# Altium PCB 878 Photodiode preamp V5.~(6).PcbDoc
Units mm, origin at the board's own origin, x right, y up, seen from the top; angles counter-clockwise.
Board outline 114 x 114 mm, 6 copper layers (Top Layer, Internal Plane 1, Dummy Ground, Dummy Power, Internal Plane 2, Bottom Layer), stack 0.534 mm thick; 182 components, 82 nets, 481 pads, 78 vias.
Unrouted connection lines stored in the file: 13.
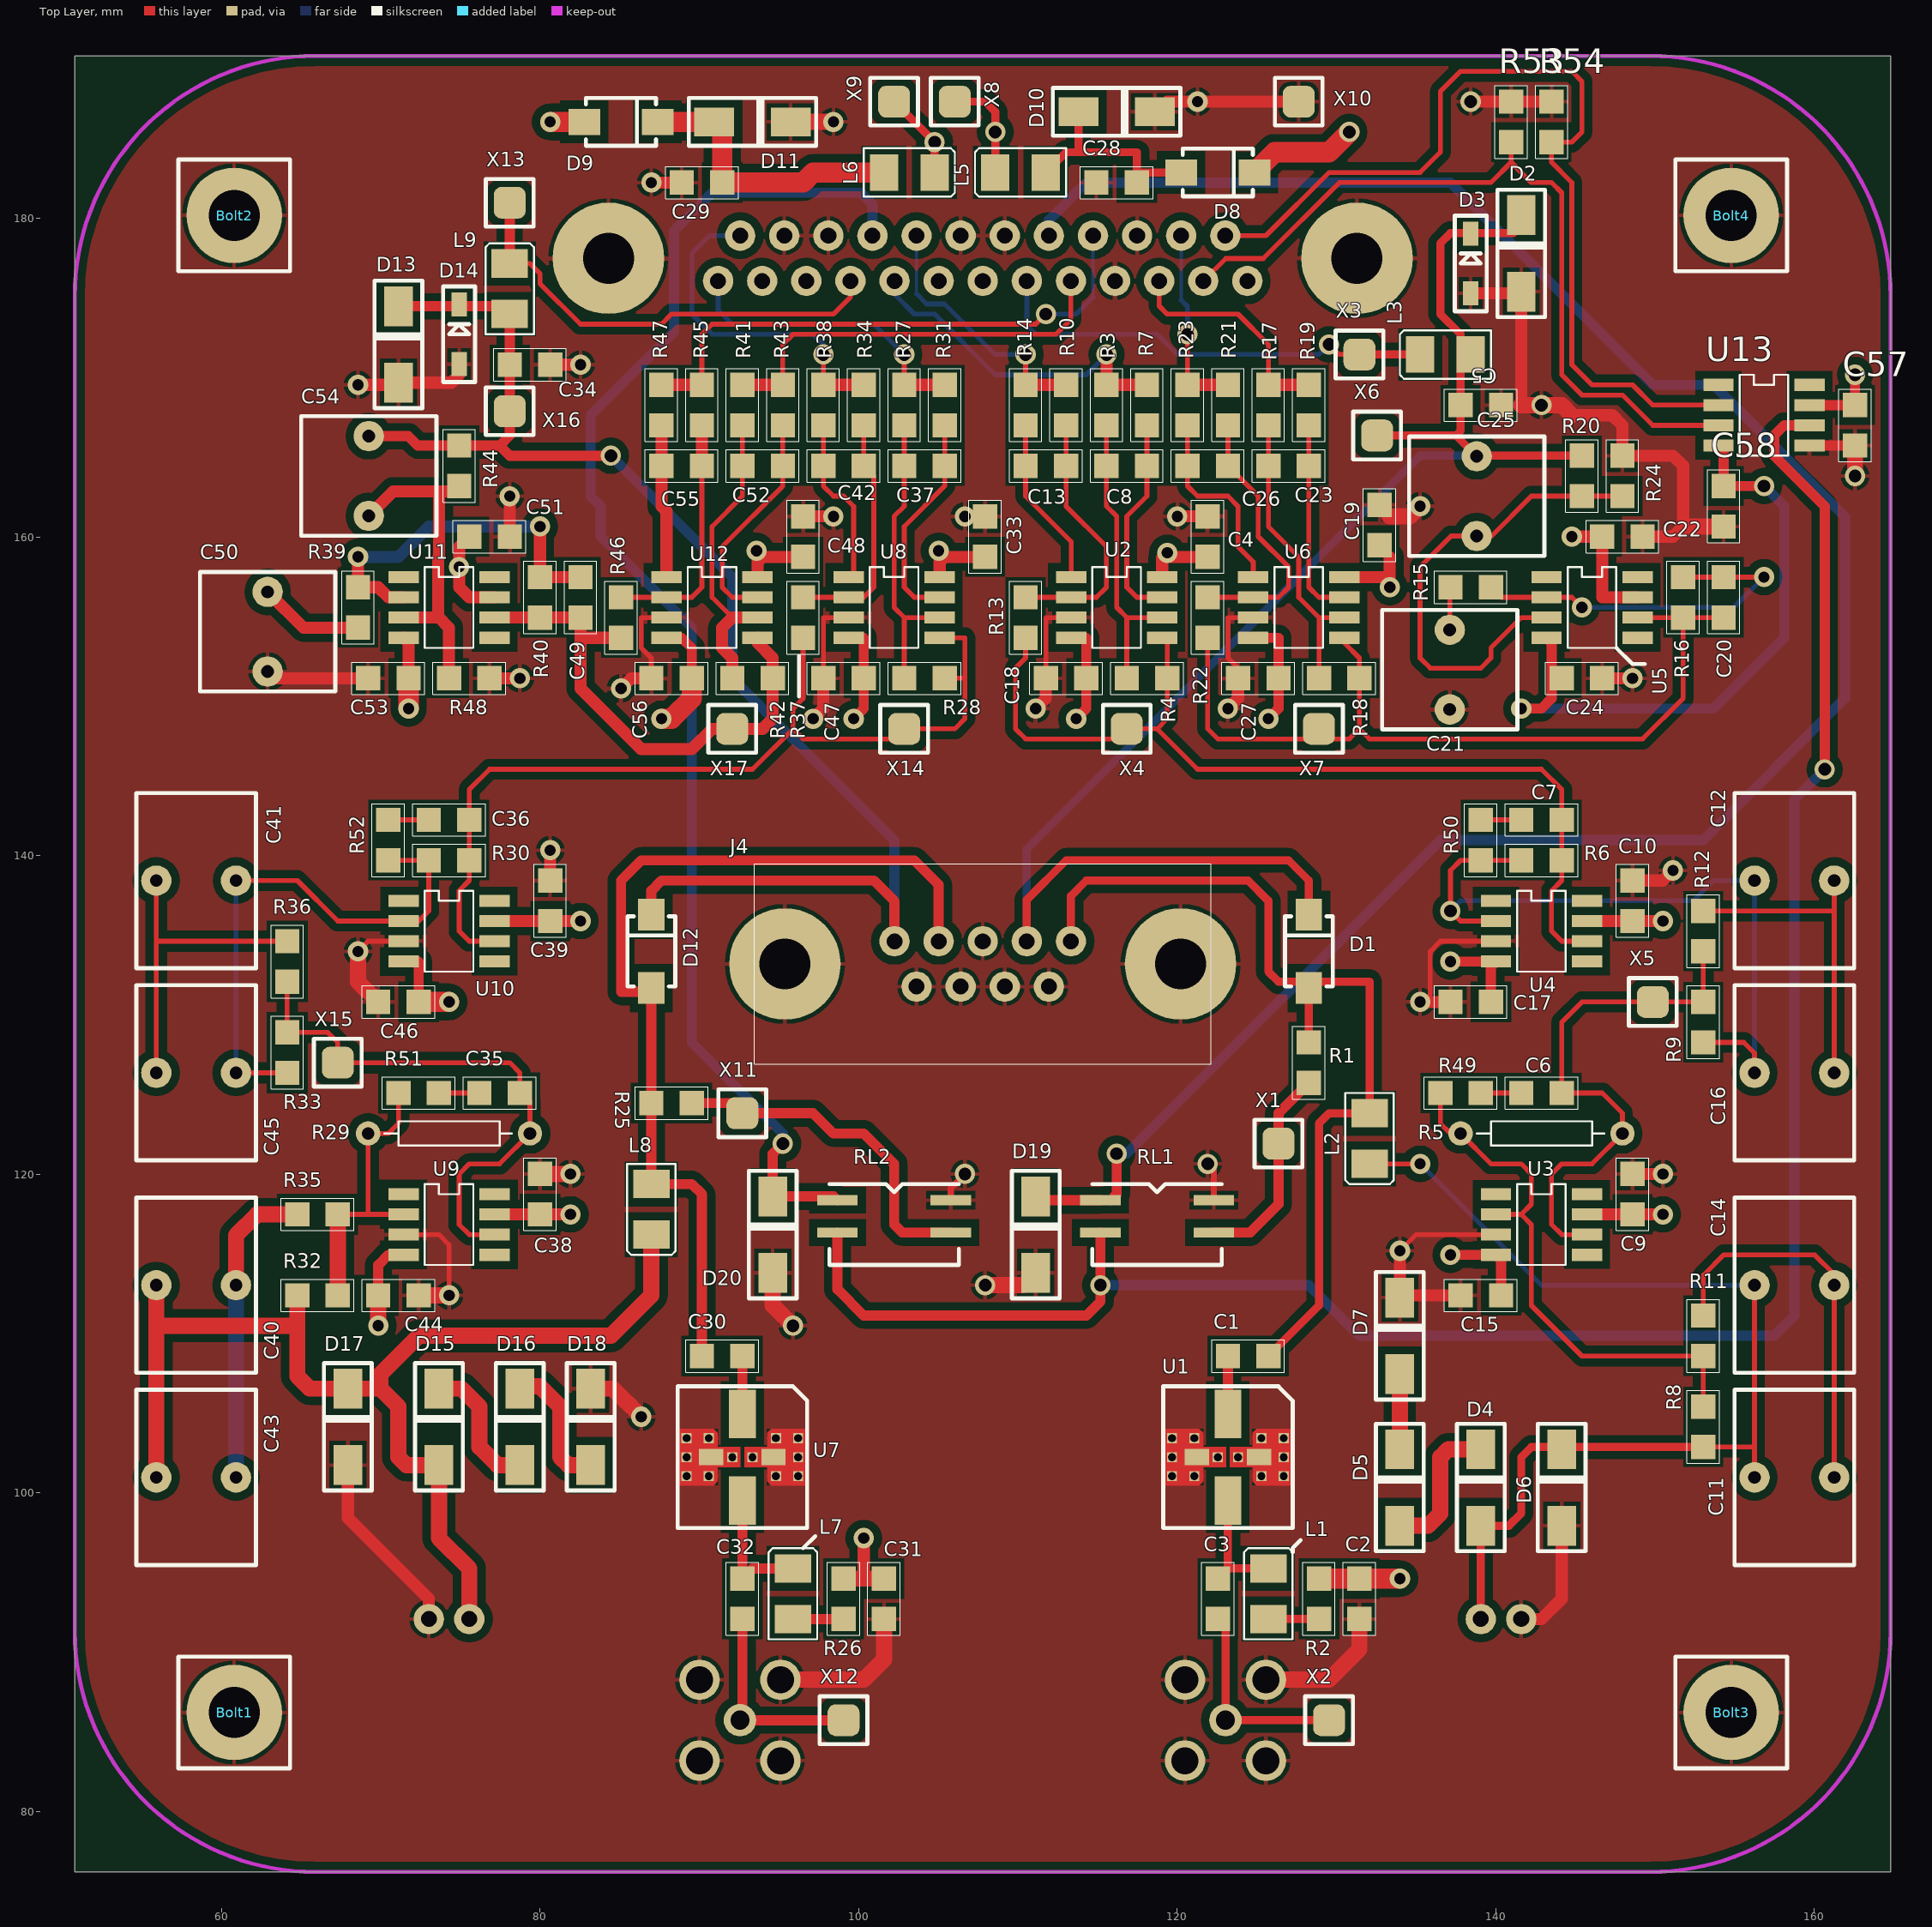
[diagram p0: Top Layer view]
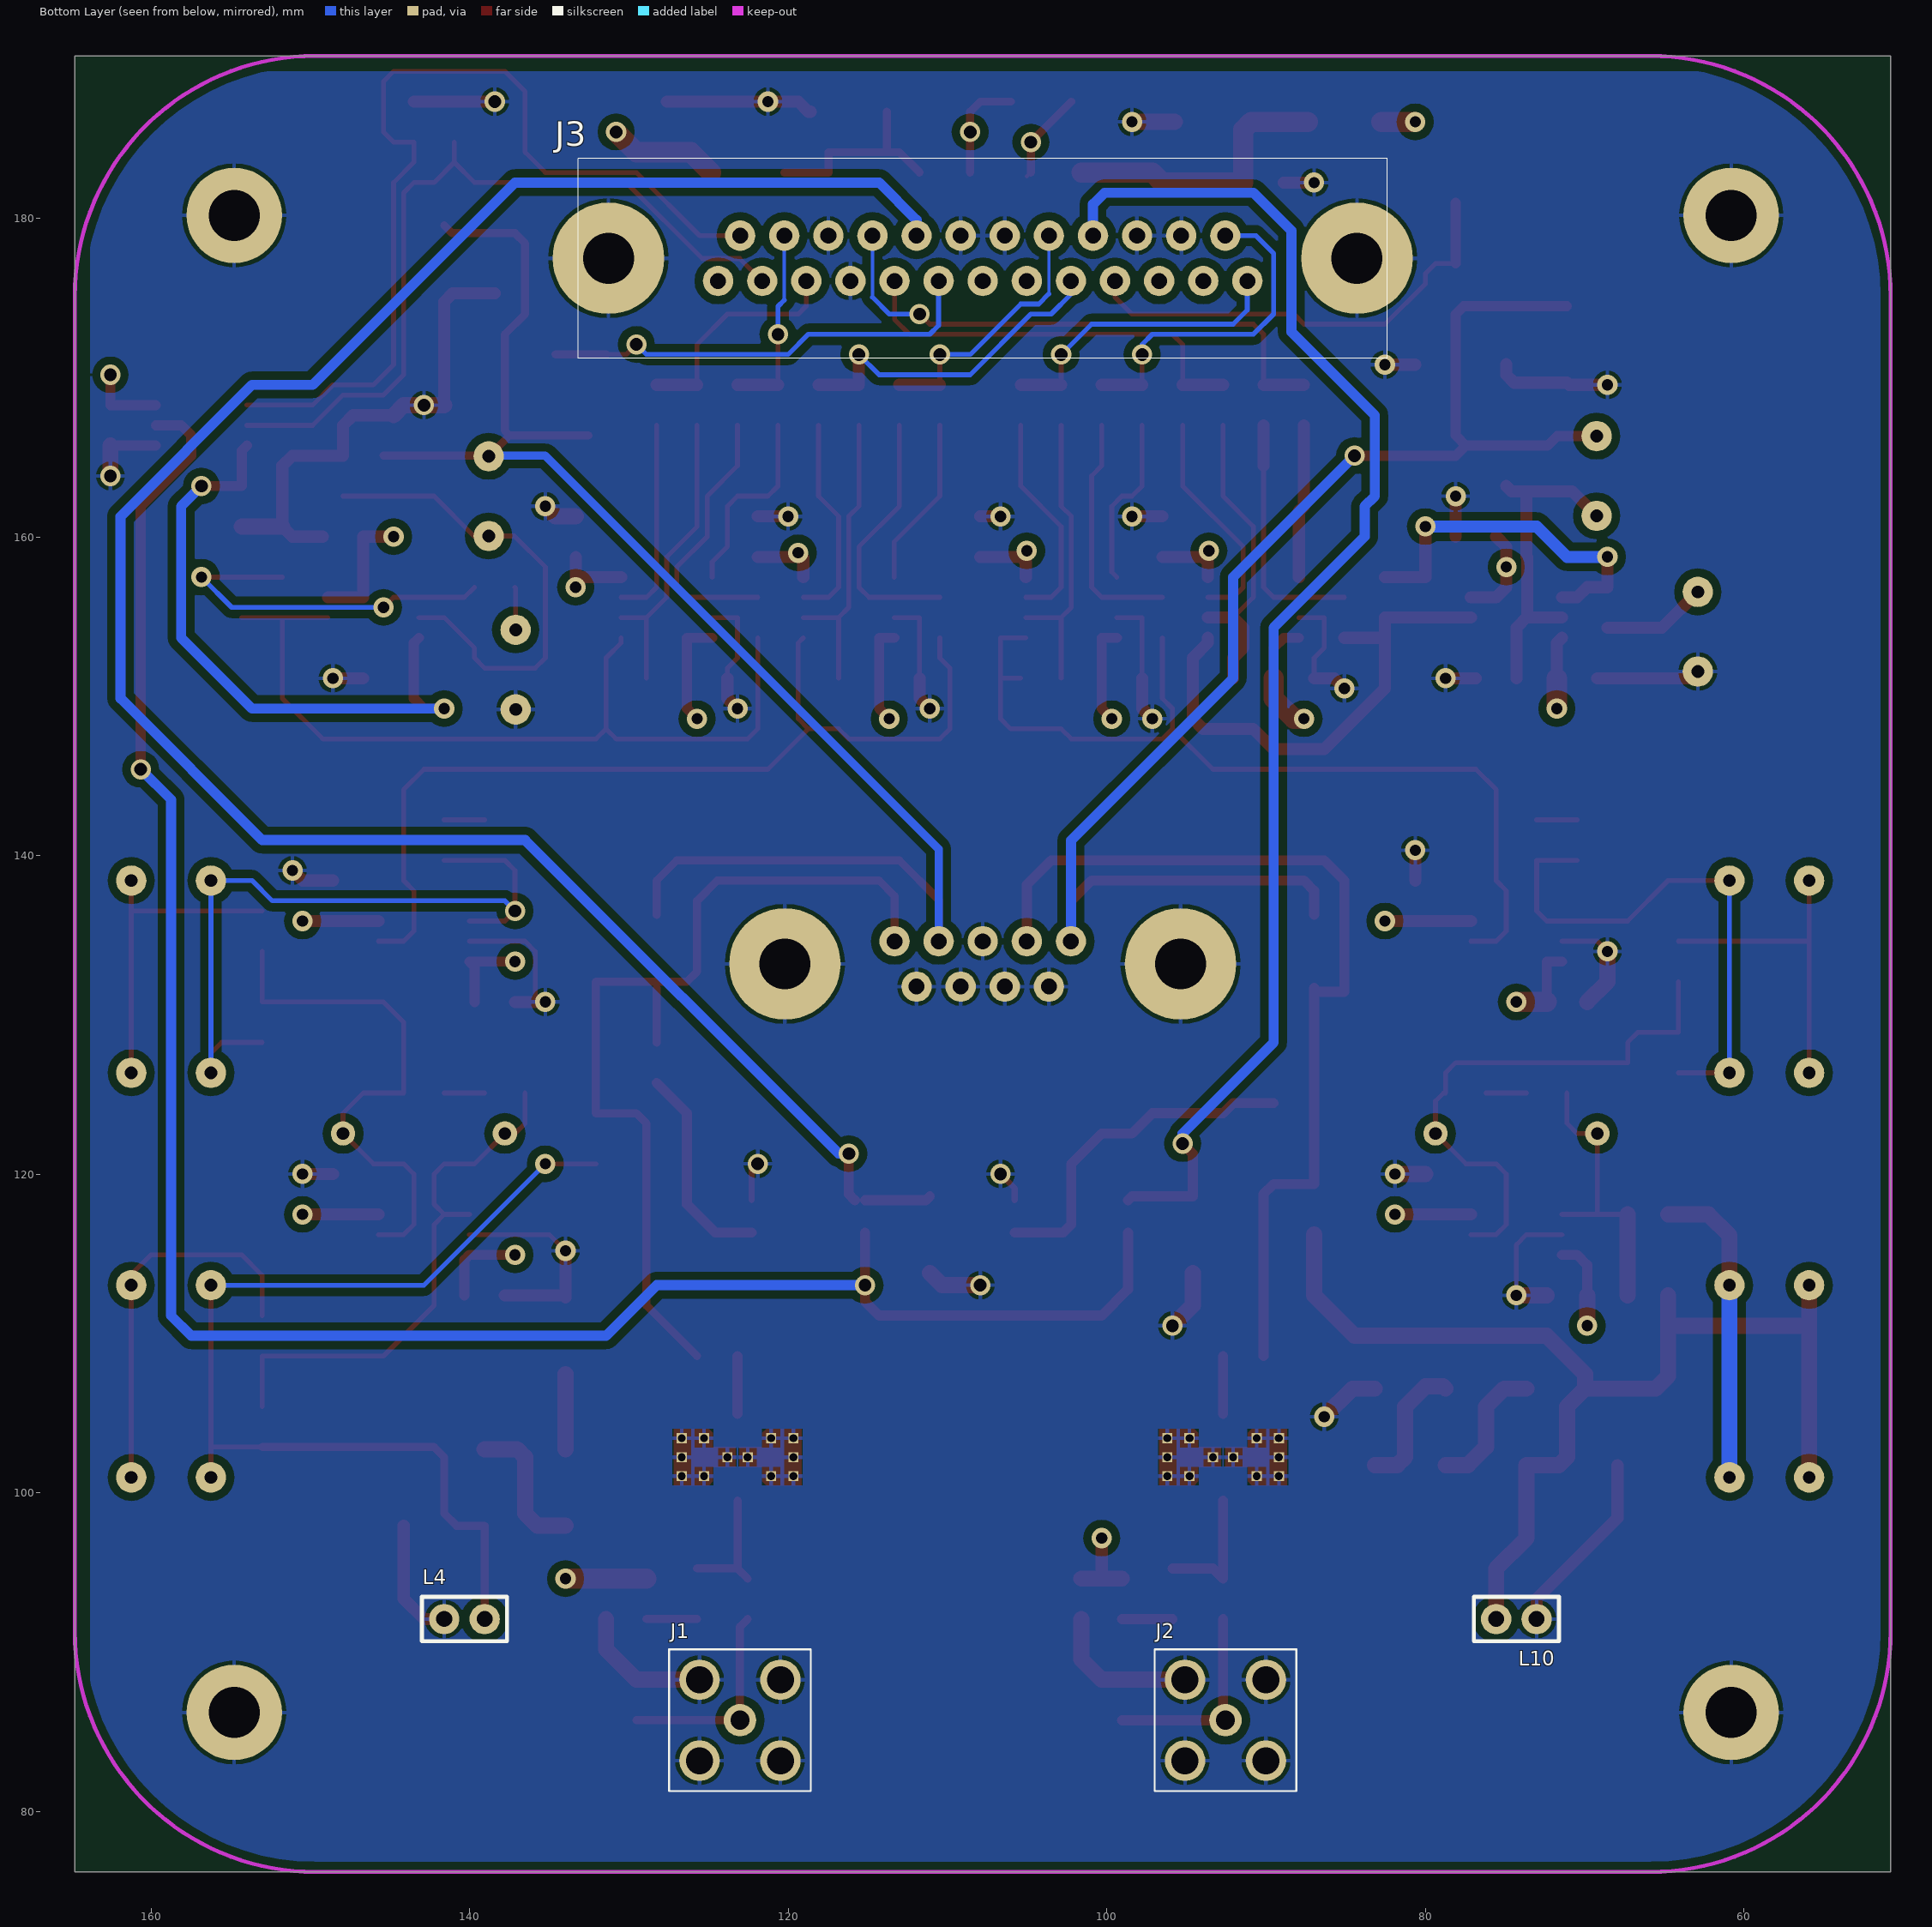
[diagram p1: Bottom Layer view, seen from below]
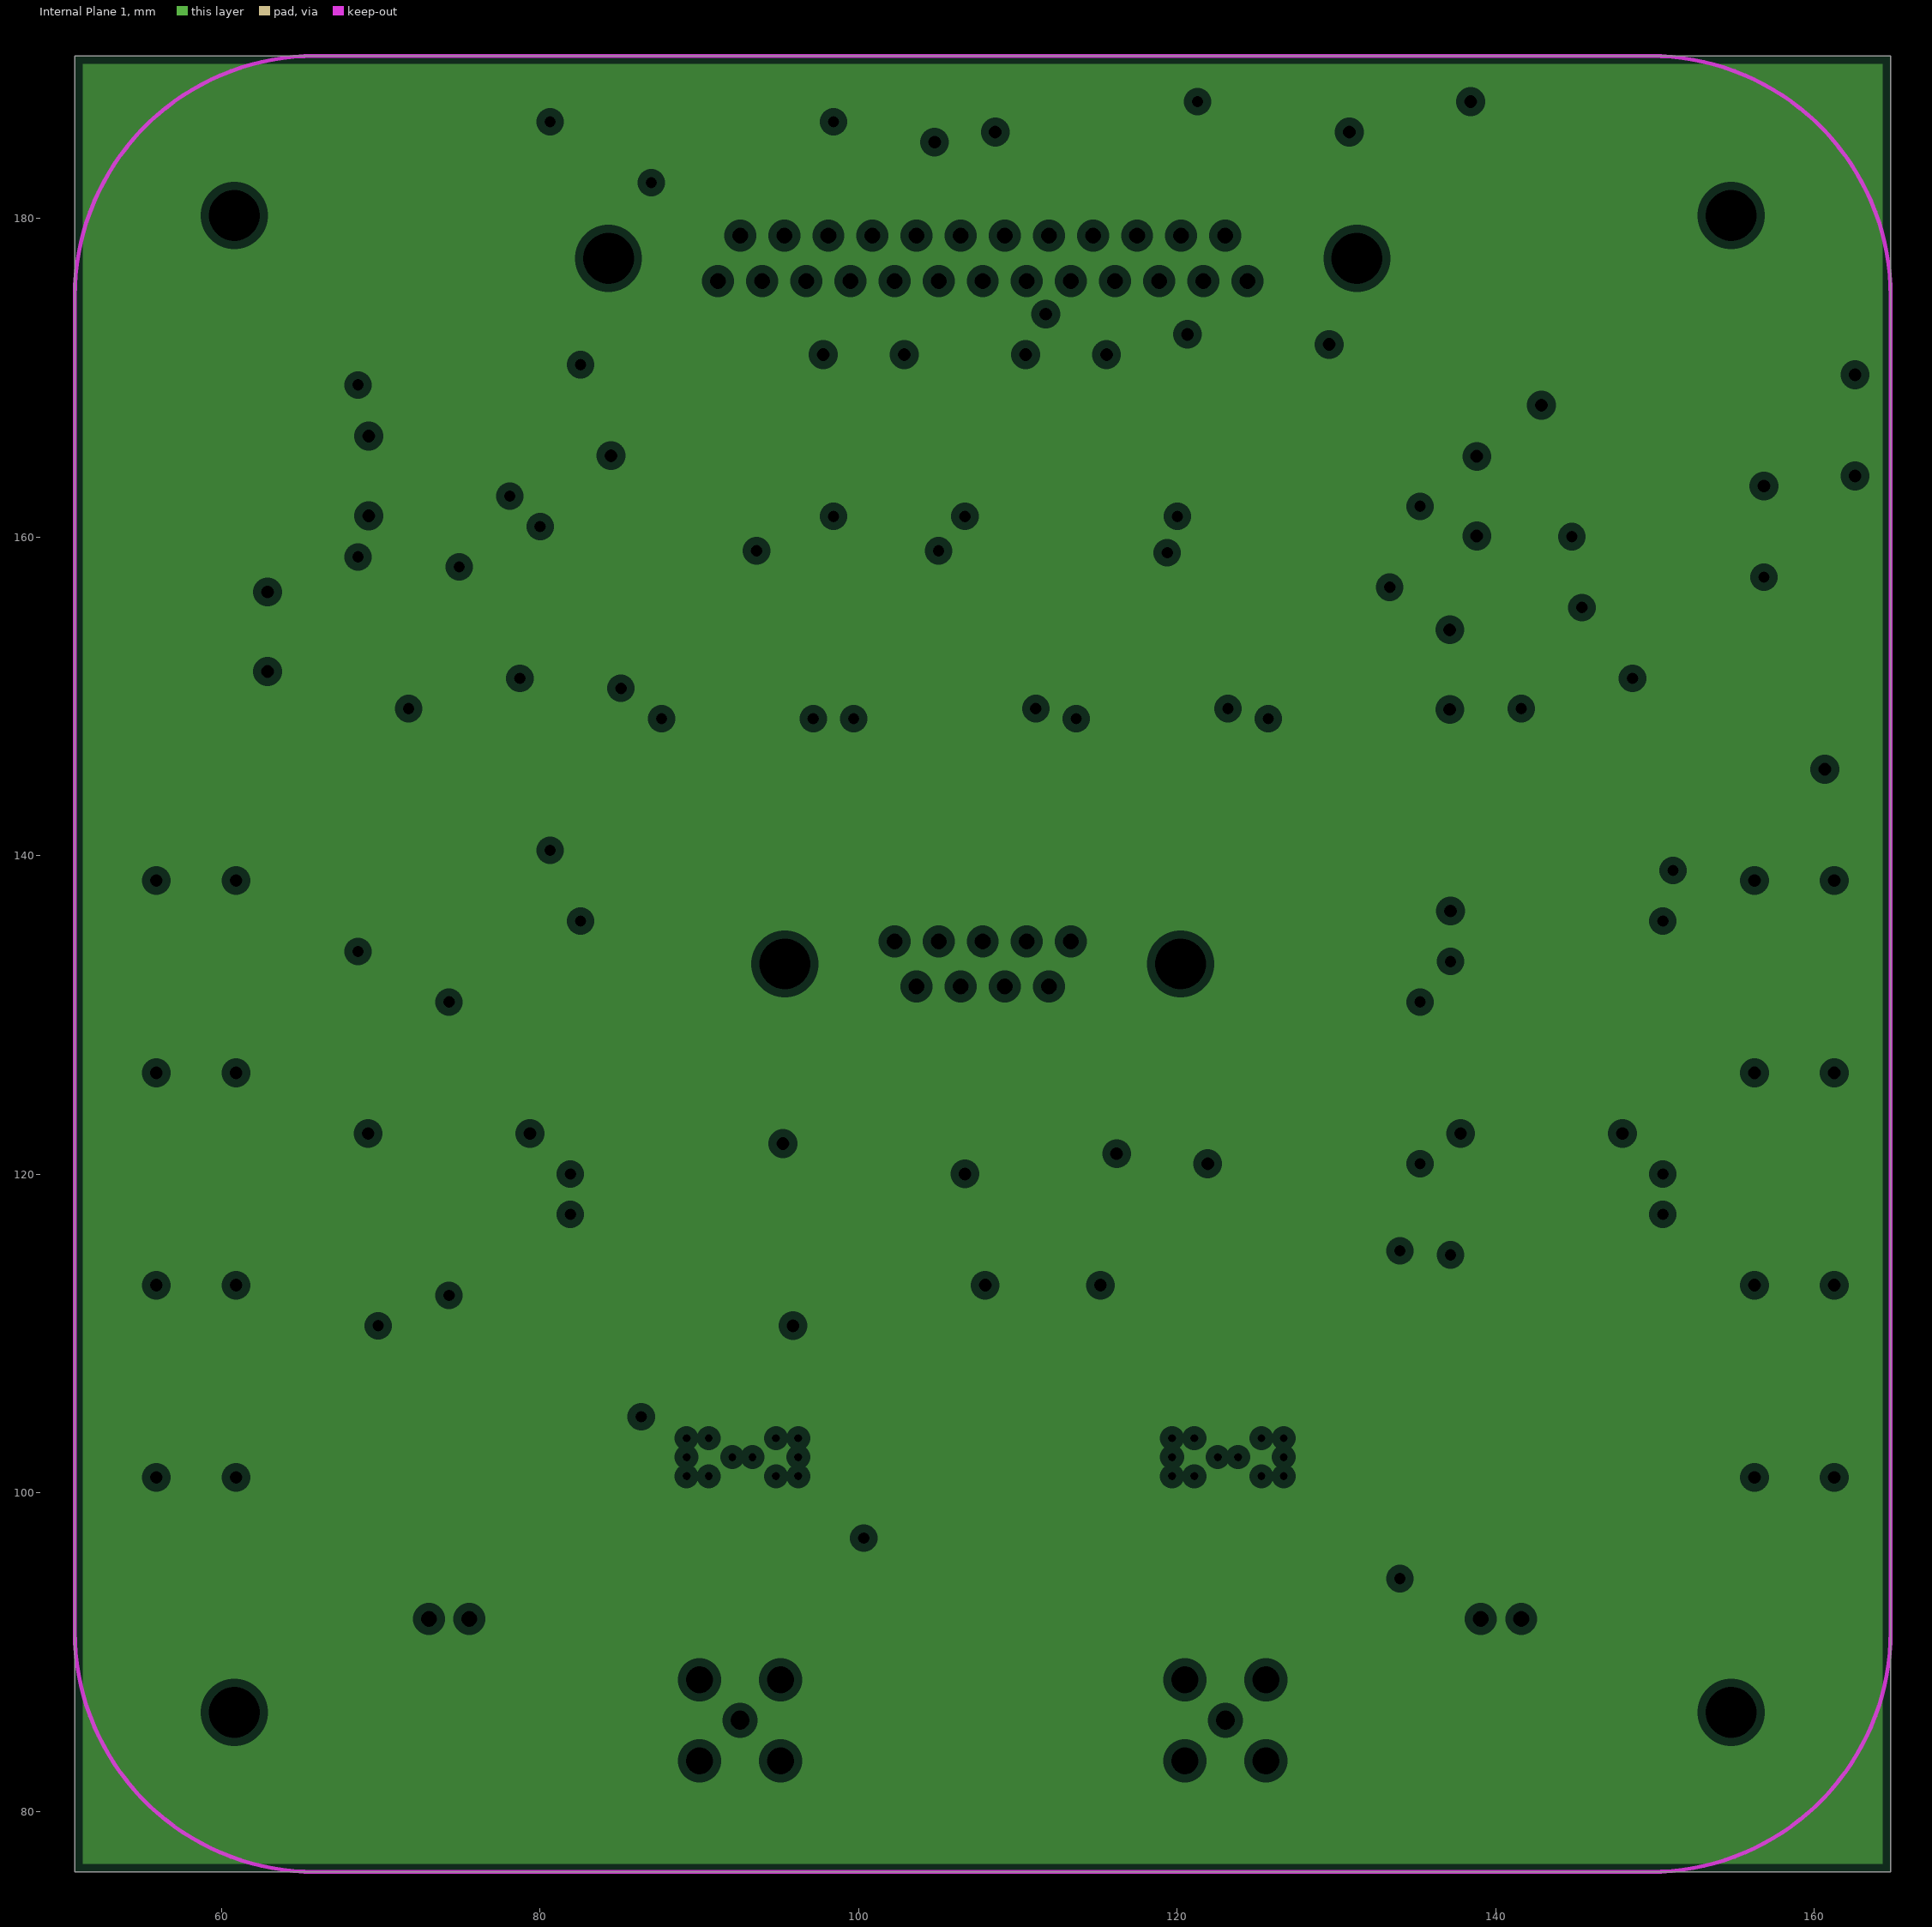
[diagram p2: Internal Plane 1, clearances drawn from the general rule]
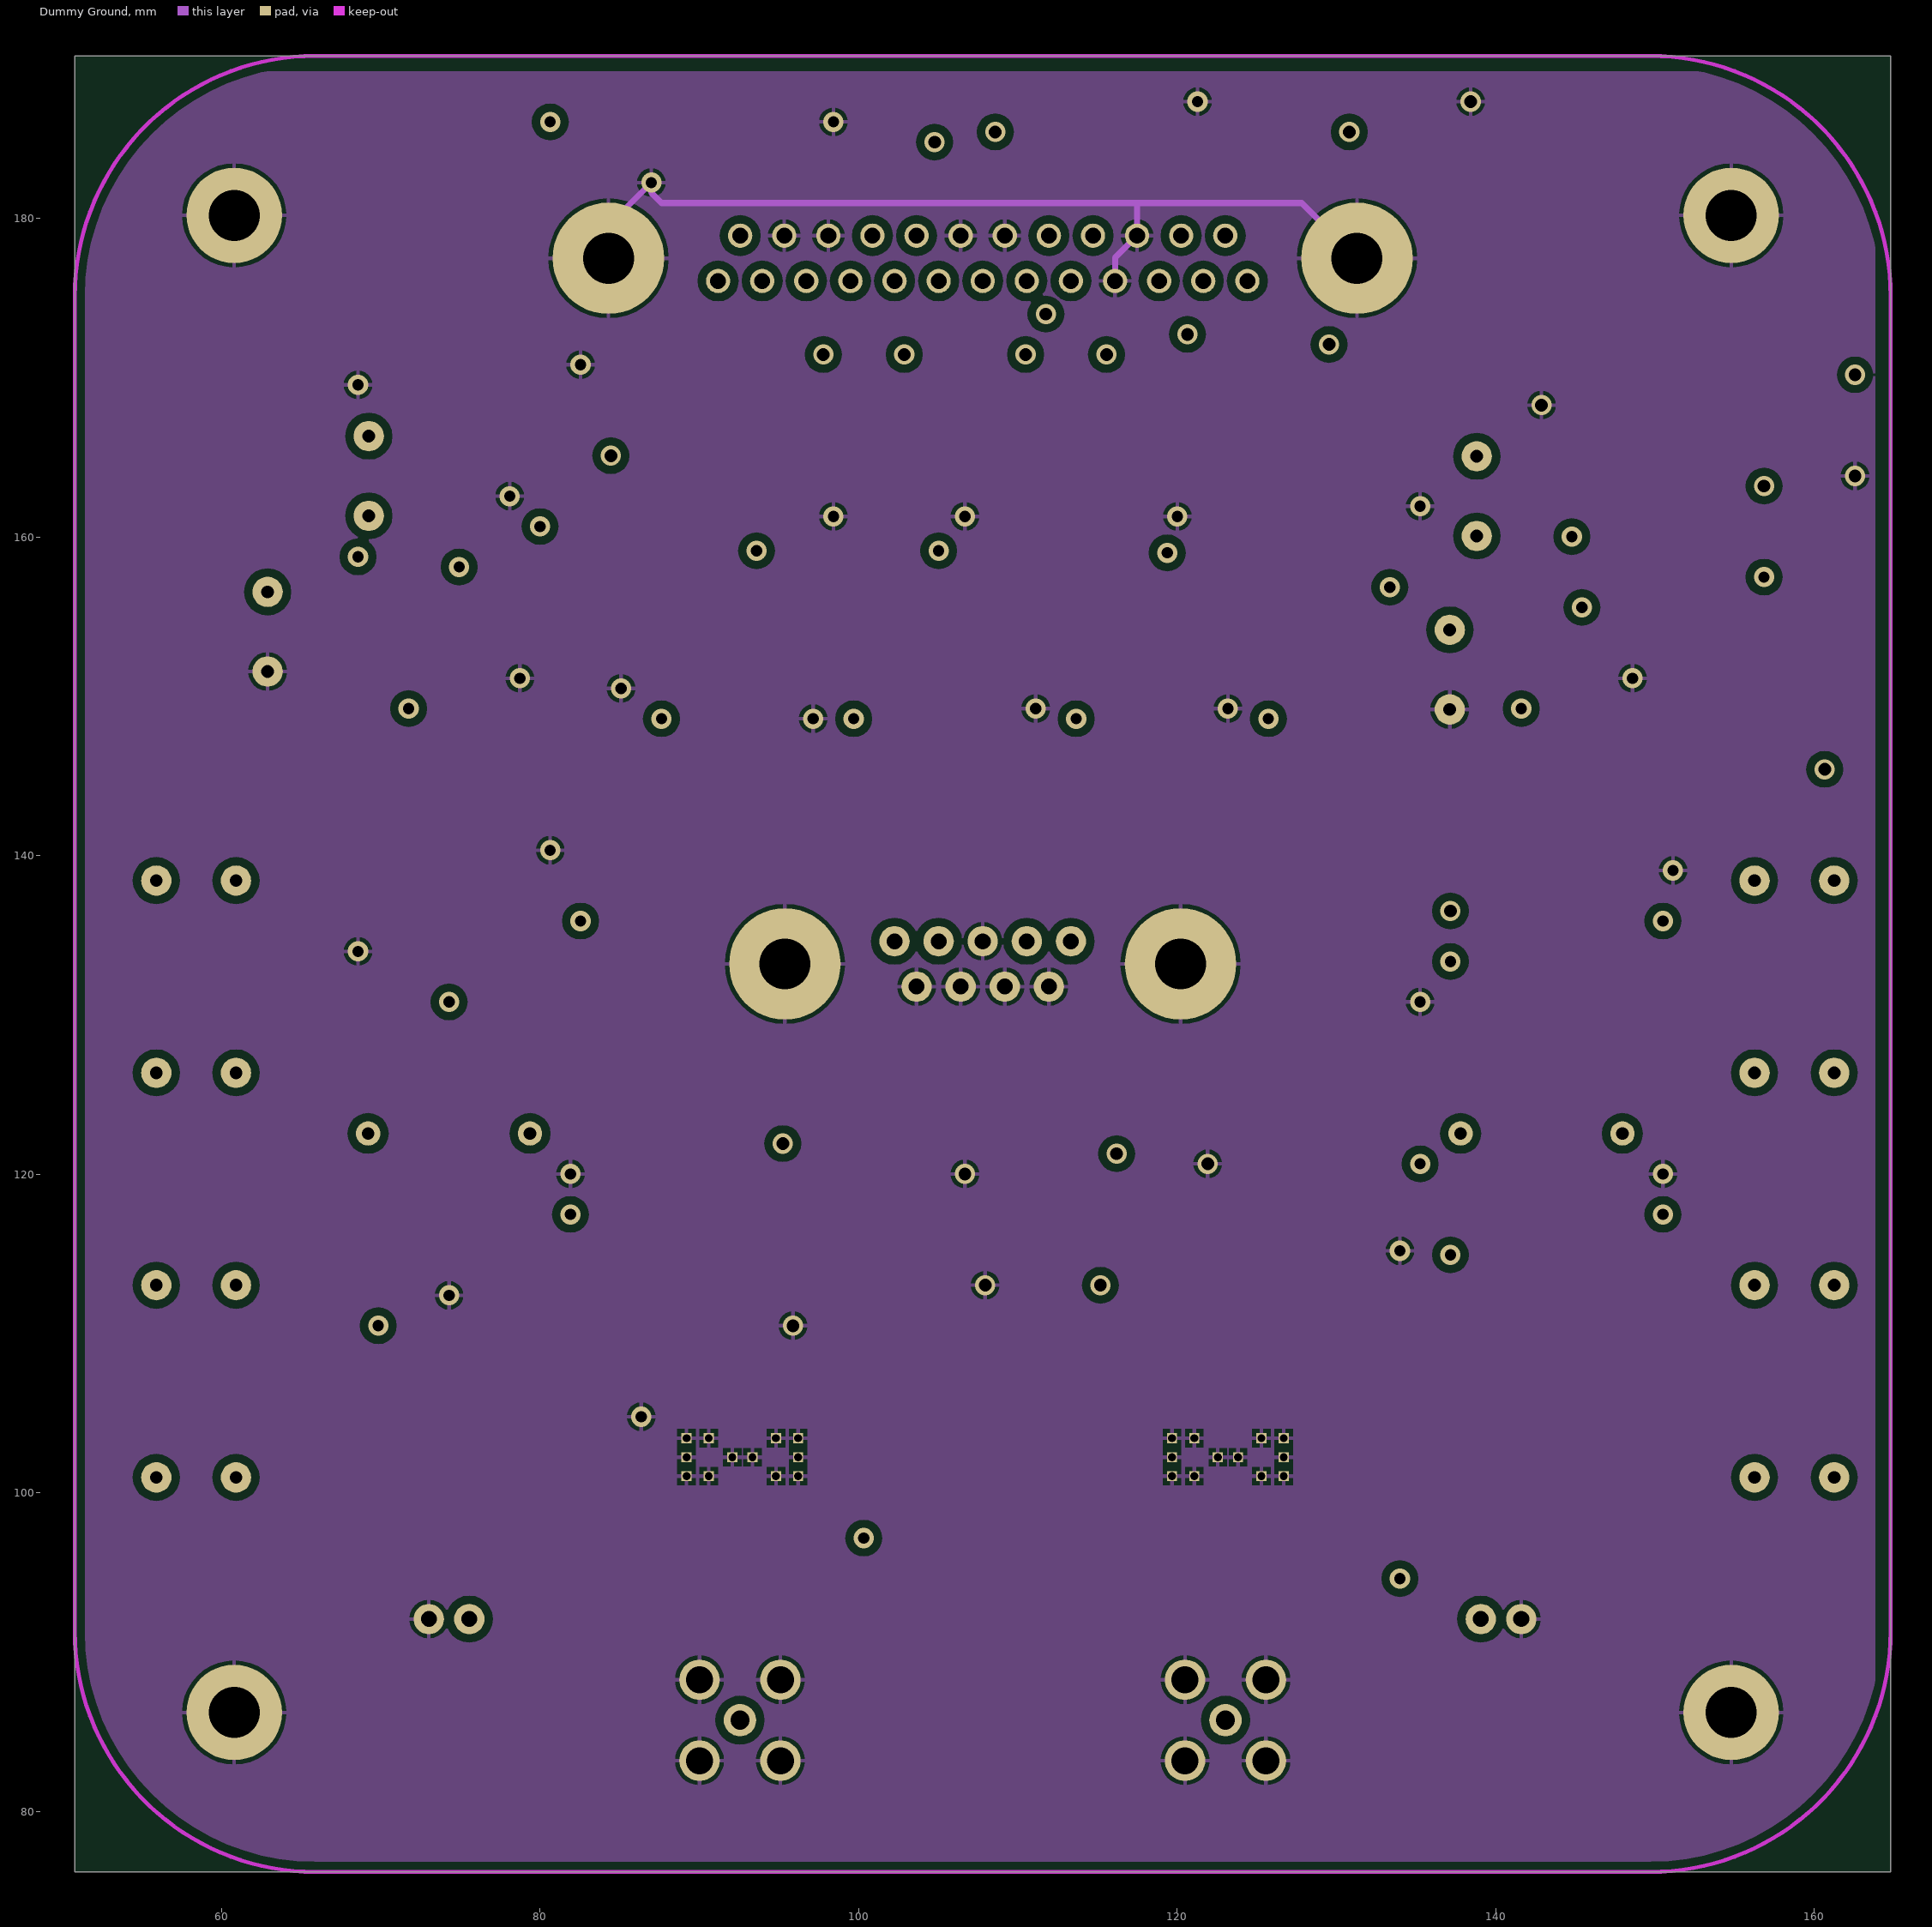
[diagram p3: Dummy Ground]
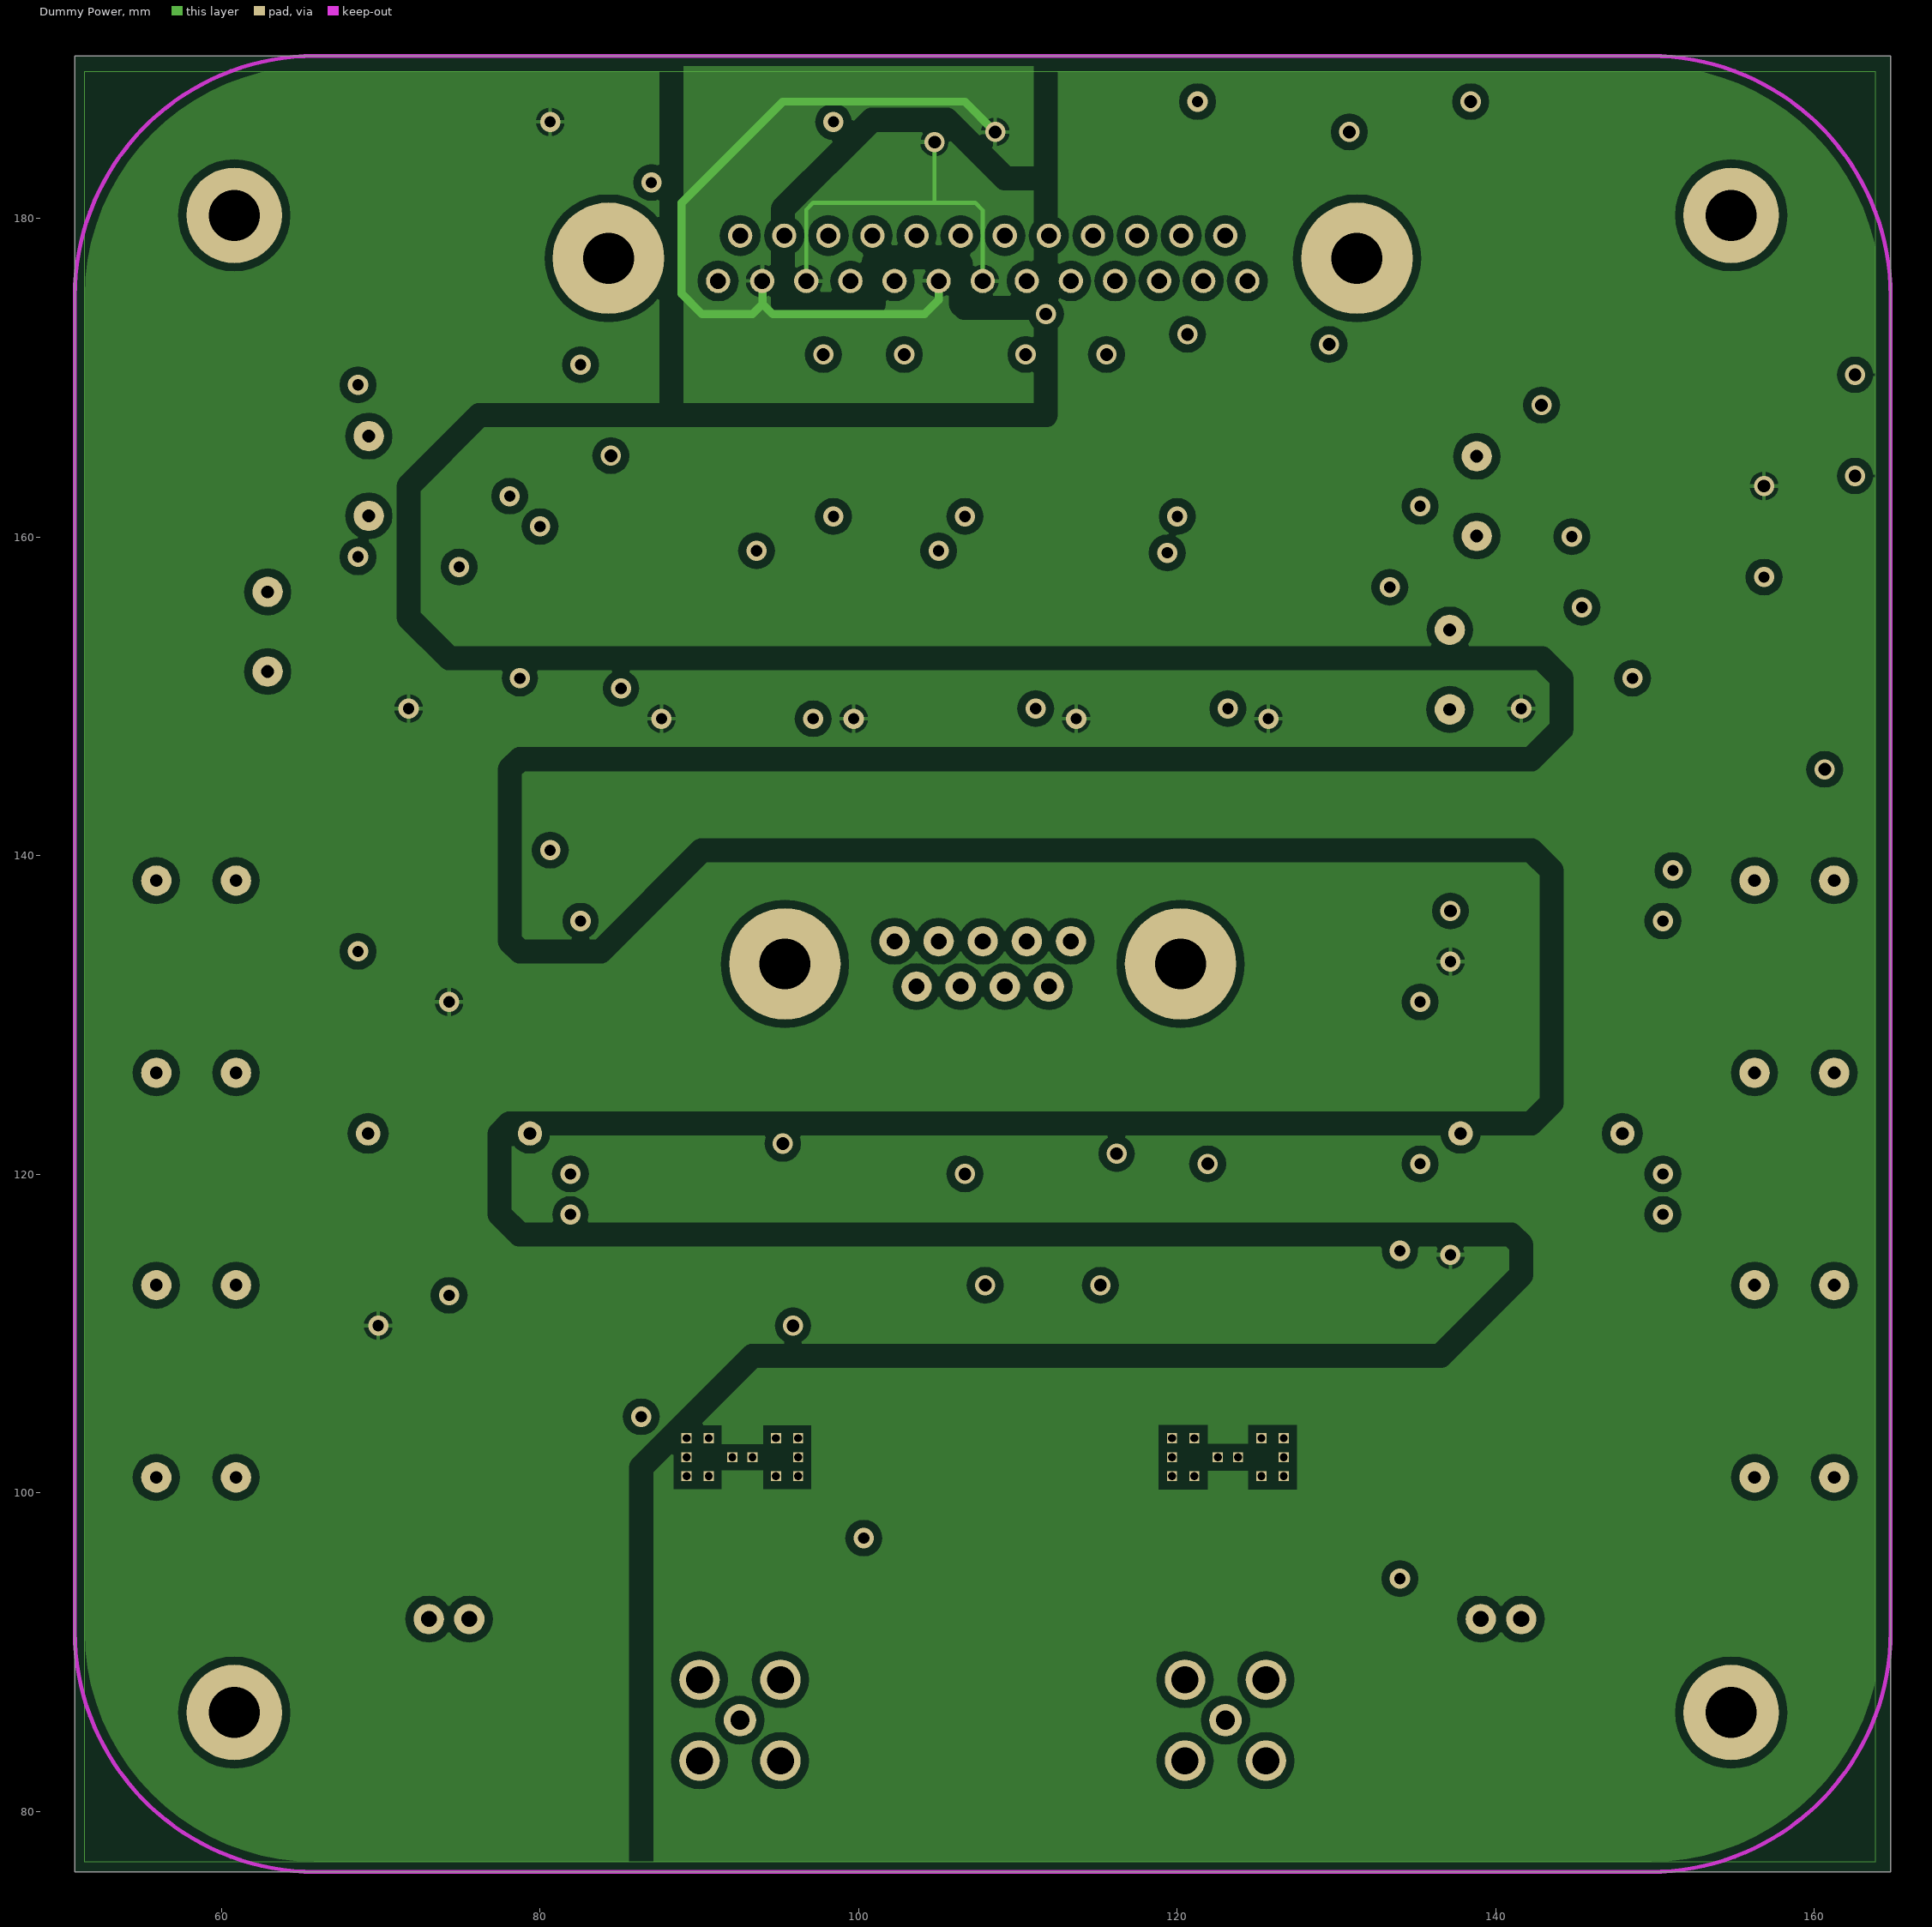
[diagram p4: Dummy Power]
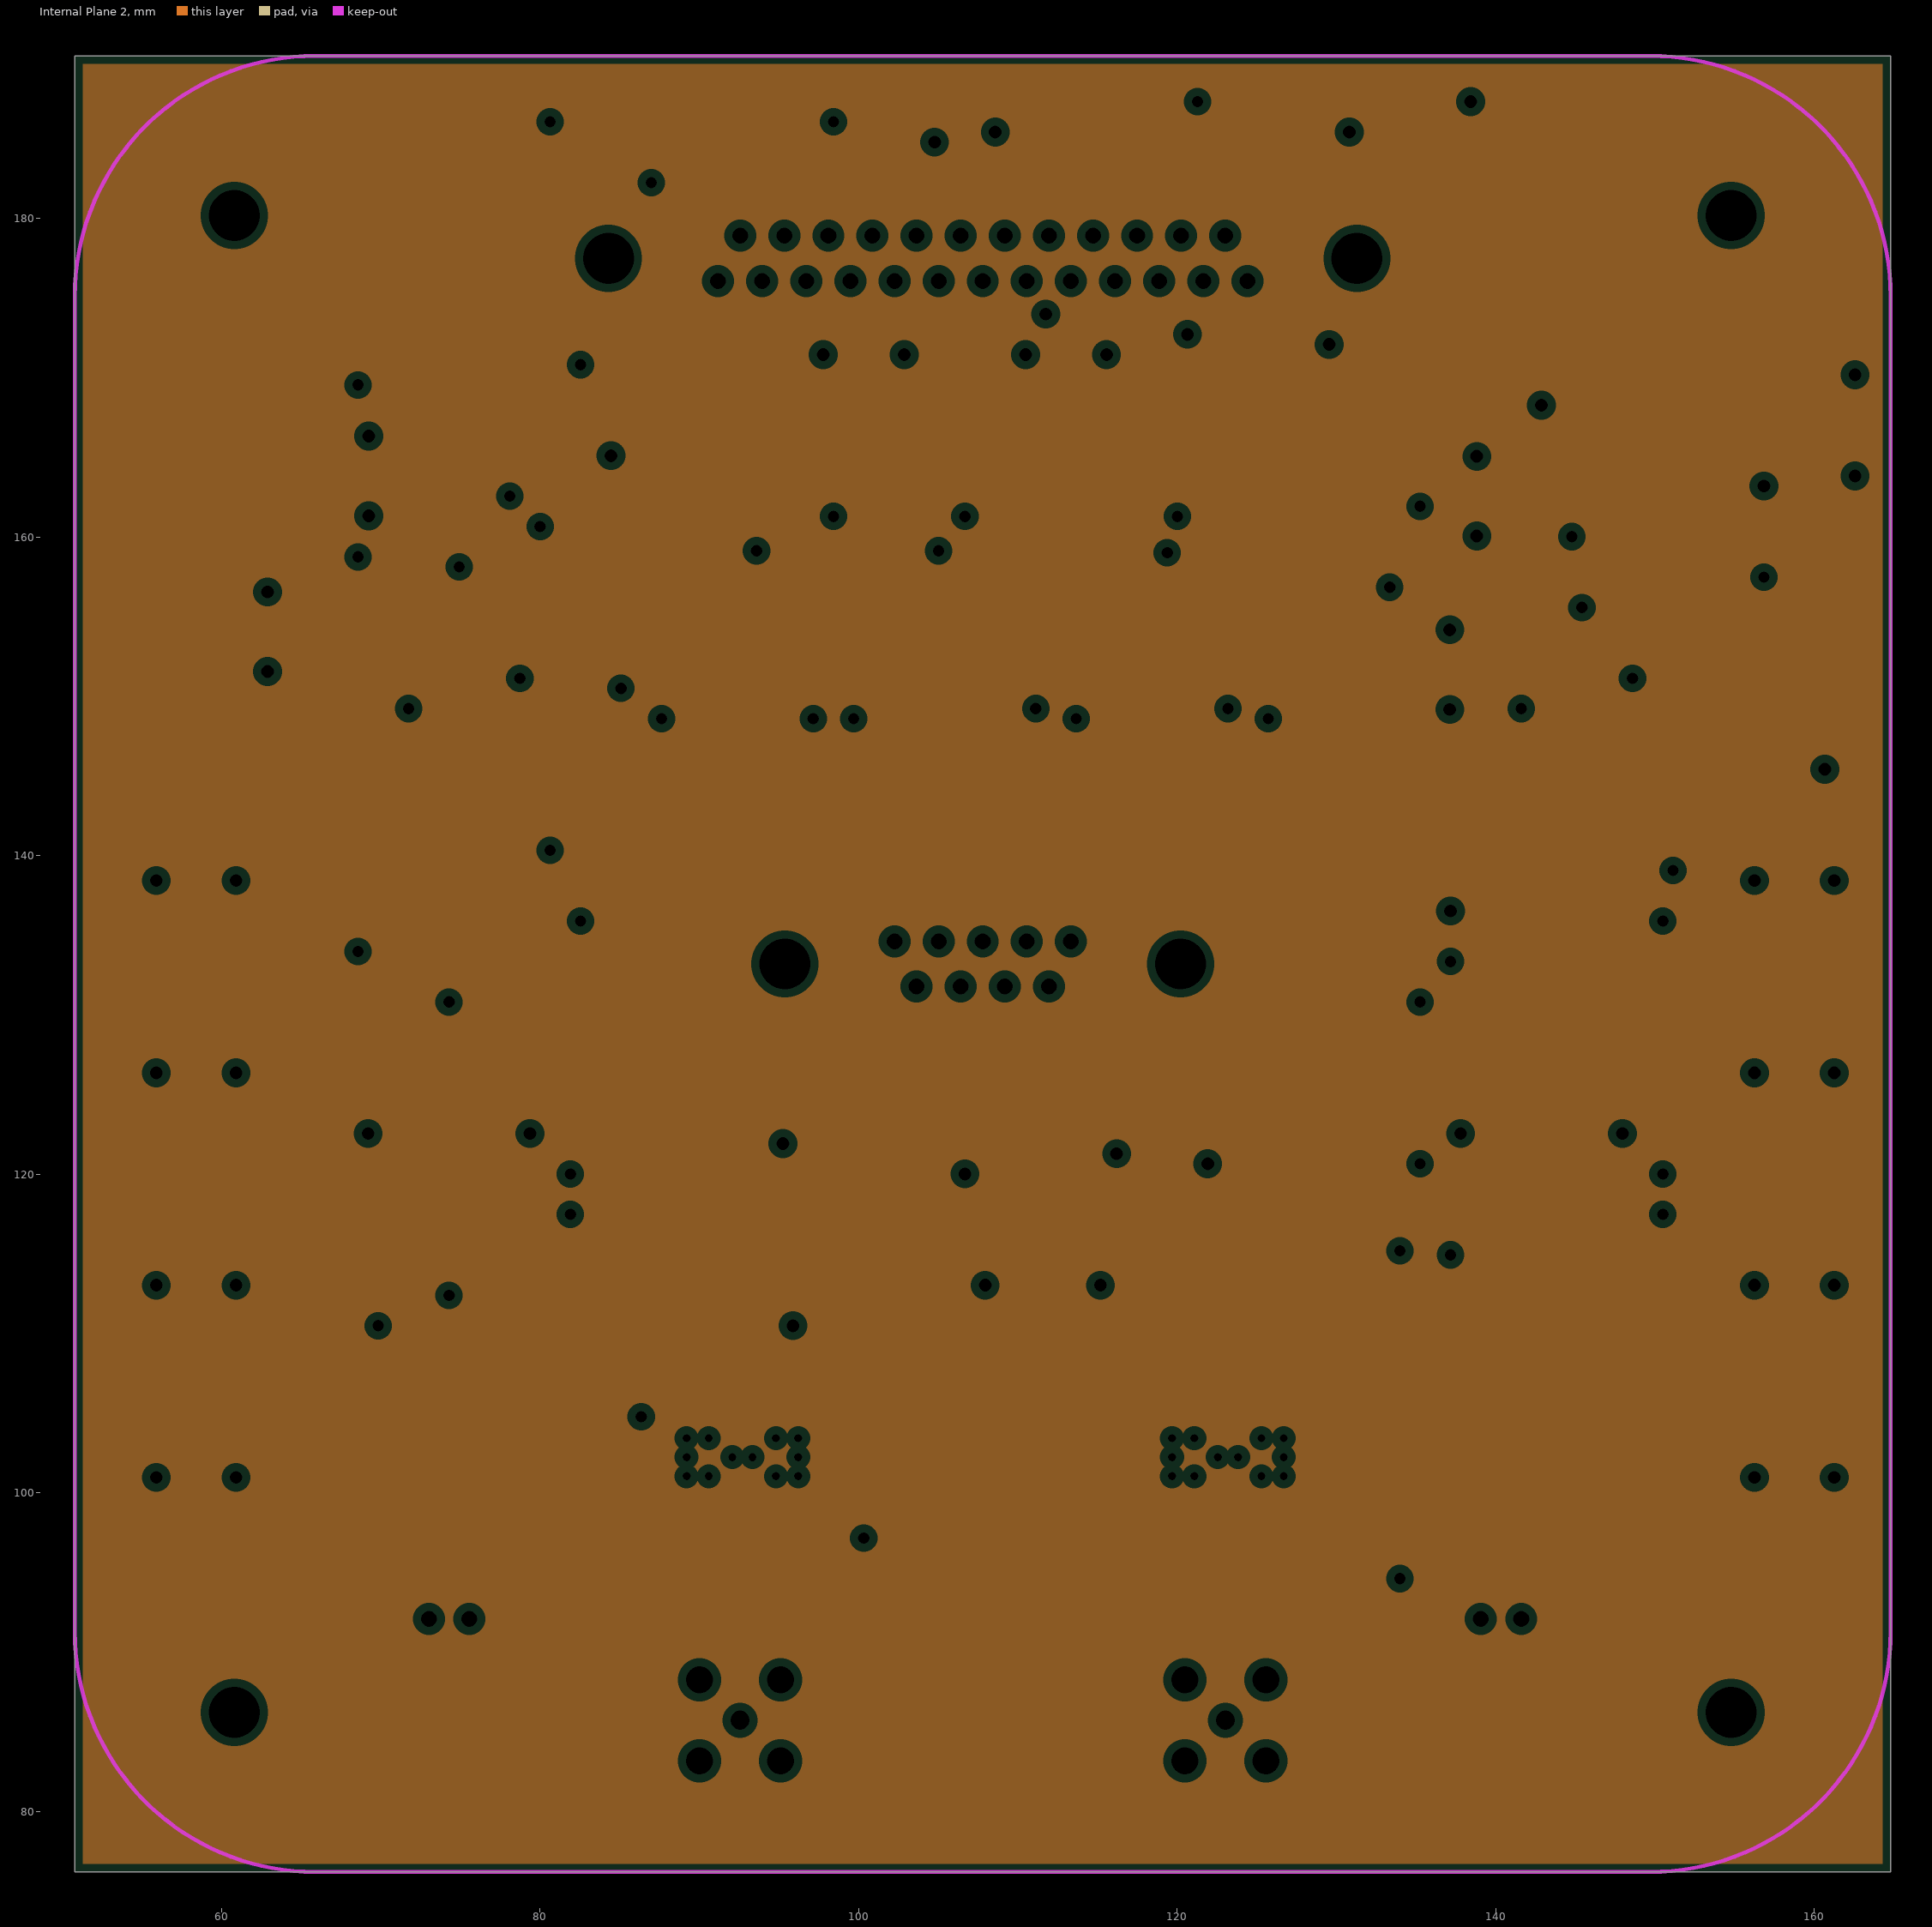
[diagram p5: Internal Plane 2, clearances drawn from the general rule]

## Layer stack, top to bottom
Top Solder: solder mask 0.0102, Solder Resist, Dk 3.5
Top Layer: signal copper 0.0356
Internal Plane 1: plane copper 0.0356
Dummy Ground: signal copper 0.036
Dummy Power: signal copper 0.036
Internal Plane 2: plane copper 0.0356
Dielectric 1: dielectric 0.32, FR-4, Dk 4.8
Bottom Layer: signal copper 0.0356
Bottom Solder: solder mask 0.0102, Solder Resist, Dk 3.5

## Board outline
50.8,76.2 164.795,76.2 164.795,190.195 50.8,190.195

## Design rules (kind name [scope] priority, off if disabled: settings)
Clearance Clearance_1 [InNamedPolygon('Top Layer-No Net')] p1: gap=0.508
Clearance [All] p2: gap=0.305 except(0.203: Track-SMDPad)
HoleSize [All] p1: absolutevalues=TRUE maxlimit=3.81 minlimit=0.025 maxpercent=80.000 minpercent=20.000
PlaneClearance [All] p1: clearance=0.508
PlaneConnect [All] p1: planeconnectstyle=Relief reliefexpansion=0.508 reliefentries=4 reliefconductorwidth=0.254 reliefairgap=0.254
PolygonConnect [All] p1: connectstyle=Relief reliefconductorwidth=0.254 reliefentries=4 polygonreliefangle="90 Angle" airgapwidth=0.254
RoutingVias [All] p1: holewidth=0.8 width=1.27 viastyle="Through Hole" minholewidth=0.5 minwidth=0.762 maxholewidth=0.8 maxwidth=1.524
SolderMaskExpansion [All] p1: expansion=0.102
Width [All] p1: maxlimit=5.08 minlimit=0.152 preferedwidth=0.305
27 further rules are at their usual default settings.

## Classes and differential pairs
component class "878 Photodiode preamp v5 P2": C30 C31 C32 C33 C34 C35 C36 C37 C38 C39 C40 C41 C42 C43 C44 C45 C46 C47 C48 C49 C50 C51 C52 C53 C54 C55 C56 D12 D13 D14 D15 D16 D17 D18 D20 J2 J3 J4 L7 L8 L9 L10 R25 R26 R27 R28 R29 R30 R31 R32 R33 R34 R35 R36 R37 R38 R39 R40 R41 R42 R43 R44 R45 R46 R47 R48 R51 R52 RL2 U7 U8 U9 U10 U11 U12 X11 X12 X13 X14 X15 X16 X17
component class "878 Photodiode preamp v5 P1": Bolt1 Bolt2 Bolt3 Bolt4 C1 C2 C3 C4 C5 C6 C7 C8 C9 C10 C11 C12 C13 C14 C15 C16 C17 C18 C19 C20 C21 C22 C23 C24 C25 C26 C27 C28 C29 C57 C58 D1 D2 D3 D4 D5 D6 D7 D8 D9 D10 D11 D19 J1 L1 L2 L3 L4 L5 L6 R1 R2 R3 R4 R5 R6 R7 R8 R9 R10 R11 R12 R13 R14 R15 R16 R17 R18 R19 R20 R21 R22 R23 R24 R49 R50 R53 R54 RL1 U1 U2 U3 U4 U5 U6 U13 X1 X2 X3 X4 X5 X6 X7 X8 X9 X10

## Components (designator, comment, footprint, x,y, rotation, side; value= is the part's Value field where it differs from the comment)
Bolt1 "Bolt M3" BOLT 60.808,86.208 r0 top
Bolt2 "Bolt M3" BOLT 60.808,180.188 r0 top
Bolt3 "Bolt M3" BOLT 154.788,86.208 r0 top
Bolt4 "Bolt M3" BOLT 154.788,180.188 r0 top
C1 "Cap200" HS0805Long 124.46,108.585 r180 top
C2 "Cap200" HS0805Long 131.445,93.345 r270 top
C3 "Cap200" HS0805Long 122.555,93.345 r270 top
C4 "Cap200" HS0805Long 121.92,160.02 r90 top
C5 "Cap200" HS0805Long 139.065,168.275 r0 top
C6 "Cap200" HS0805Long 142.875,125.095 r0 top
C7 "Cap200" HS0805Long 142.875,142.24 r0 top
C8 "Cap200" HS0805Long 116.84,164.465 r0 top
C9 "Cap200" HS0805Long 148.59,118.745 r90 top
C10 "Cap200" HS0805Long 148.59,137.16 r90 top
C11 "Cap200" "MKS2 7.2 11" 158.75,100.965 r0 top
C12 "Cap200" "MKS2 7.2 11" 158.75,138.43 r180 top
C13 "Cap200" HS0805Long 111.76,164.465 r180 top
C14 "Cap200" "MKS2 7.2 11" 158.75,113.03 r0 top
C15 "Cap200" HS0805Long 139.065,112.395 r180 top
C16 "Cap200" "MKS2 7.2 11" 158.75,126.365 r180 top
C17 "Cap200" HS0805Long 138.43,130.81 r180 top
C18 "Cap200" HS0805Long 113.03,151.13 r180 top
C19 "Cap200" HS0805Long 132.715,160.744 r90 top
C20 "Cap200" HS0805Long 154.305,156.21 r270 top
C21 "Cap200" "MKS2 7.2 8.5" 137.118,151.672 r90 top
C22 "Cap200" HS0805Long 147.955,160.02 r0 top
C23 "Cap200" HS0805Long 127,164.465 r0 top
C24 "Cap200" HS0805Long 145.415,151.13 r0 top
C25 "Cap200" "MKS2 7.2 8.5" 138.813,162.56 r270 top
C26 "Cap200" HS0805Long 121.92,164.465 r180 top
C27 "Cap200" HS0805Long 125.095,151.13 r180 top
C28 "Cap200" HS0805Long 116.205,182.245 r180 top
C29 "Cap200" HS0805Long 90.17,182.245 r180 top
C30 "Cap200" HS0805Long 91.44,108.585 r0 top
C31 "Cap200" HS0805Long 101.6,93.345 r270 top
C32 "Cap200" HS0805Long 92.71,93.345 r270 top
C33 "Cap200" HS0805Long 107.95,160.02 r90 top
C34 "Cap200" HS0805Long 79.375,170.815 r0 top
C35 "Cap200" HS0805Long 77.47,125.095 r0 top
C36 "Cap200" HS0805Long 74.295,142.24 r0 top
C37 "Cap200" HS0805Long 104.14,164.465 r0 top
C38 "Cap200" HS0805Long 80.01,118.745 r90 top
C39 "Cap200" HS0805Long 80.645,137.16 r90 top
C40 "Cap200" "MKS2 7.2 11" 58.42,113.03 r0 top
C41 "Cap200" "MKS2 7.2 11" 58.42,138.43 r0 top
C42 "Cap200" HS0805Long 99.06,164.465 r180 top
C43 "Cap200" "MKS2 7.2 11" 58.42,100.965 r0 top
C44 "Cap200" HS0805Long 71.12,112.395 r0 top
C45 "Cap200" "MKS2 7.2 11" 58.42,126.365 r0 top
C46 "Cap200" HS0805Long 71.12,130.81 r180 top
C47 "Cap200" HS0805Long 99.06,151.13 r180 top
C48 "Cap200" HS0805Long 96.52,160.02 r90 top
C49 "Cap200" HS0805Long 82.55,156.21 r270 top
C50 "Cap200" "MKS2 7.2 8.5" 62.907,154.051 r90 top
C51 "Cap200" HS0805Long 76.835,160.02 r0 top
C52 "Cap200" HS0805Long 93.98,164.465 r0 top
C53 "Cap200" HS0805Long 70.485,151.13 r180 top
C54 "Cap200" "MKS2 7.2 8.5" 69.257,163.827 r270 top
C55 "Cap200" HS0805Long 88.9,164.465 r180 top
C56 "Cap200" HS0805Long 88.265,151.13 r180 top
C57 "Cap200" HS0805Long 162.56,167.005 r90 top
C58 "Cap200" HS0805Long 154.305,161.925 r270 top
D1 "60V 1A" SMA 128.27,133.985 r270 top
D2 "SMAJxxCA" DO214AC 141.605,177.8 r270 top
D3 "60V 1A" SOD123 138.43,177.165 r270 top
D4 "1N4007" DO214AC 139.065,100.33 r270 top
D5 "1N4007" DO214AC 133.985,100.33 r270 top
D6 "1N4007" DO214AC 144.145,100.33 r270 top
D7 "1N4007" DO214AC 133.985,109.855 r270 top
D8 "60V 1A" SMA 122.555,182.88 r180 top
D9 "60V 1A" SMA 85.09,186.055 r180 top
D10 "SMAJxxCA" DO214AC 116.205,186.69 r180 top
D11 "SMAJxxCA" DO214AC 93.345,186.055 r180 top
D12 "60V 1A" SMA 86.995,133.985 r270 top
D13 "SMAJxxCA" DO214AC 71.12,172.085 r270 top
D14 "60V 1A" SOD123 74.93,172.72 r270 top
D15 "1N4007" DO214AC 73.66,104.14 r270 top
D16 "1N4007" DO214AC 78.74,104.14 r270 top
D17 "1N4007" DO214AC 67.945,104.14 r270 top
D18 "1N4007" DO214AC 83.185,104.14 r270 top
D19 "1N4004" DO214AC 111.125,116.205 r270 top
D20 "1N4004" DO214AC 94.615,116.205 r270 top
J1 "SMA" "PCB SMB" 123.038,85.725 r180 bottom
J2 "SMA" "PCB SMB" 92.558,85.725 r180 bottom
J3 "D connector 25 way" "D Socket Straight PCB 25 Way" 107.798,177.49 r0 bottom
J4 "D connector 9 way" "D Plug Straight PCB 9 Way" 107.798,133.198 r0 top
L1 "Inductor" HS1210 125.73,93.98 r270 top
L2 "Inductor" HS1210 132.08,121.92 r90 top
L3 "Inductor" HS1210 136.525,171.45 r0 top
L4 "Inductor" "2 way 0.1\"" 140.335,92.075 r180 bottom
L5 "Inductor" HS1210 109.855,182.88 r0 top
L6 "Inductor" HS1210 103.505,182.88 r180 top
L7 "Inductor" HS1210 95.885,93.98 r270 top
L8 "Inductor" HS1210 86.995,117.475 r90 top
L9 "Inductor" HS1210 78.105,175.895 r270 top
L10 "Inductor" "2 way 0.1\"" 74.295,92.075 r0 bottom
R1 "Res" hs0805long 128.27,127 r90 top
R2 "Res" hs0805long 128.905,93.345 r90 top
R3 "Res" hs0805long 115.57,168.275 r90 top
R4 "Res" hs0805long 118.11,151.13 r180 top
R5 "Res" "Res 0.4\"" 142.875,122.555 r0 top
R6 "Res" hs0805long 142.875,139.7 r0 top
R7 "Res" hs0805long 118.11,168.275 r90 top
R8 "Res" hs0805long 153.035,104.14 r90 top
R9 "Res" hs0805long 153.035,129.54 r270 top
R10 "Res" hs0805long 113.03,168.275 r90 top
R11 "Res" hs0805long 153.035,109.855 r270 top
R12 "Res" hs0805long 153.035,135.255 r90 top
R13 "Res" hs0805long 110.49,154.94 r90 top
R14 "Res" hs0805long 110.49,168.275 r90 top
R15 "Res" hs0805long 138.43,156.845 r180 top
R16 "Res" hs0805long 151.765,156.21 r270 top
R17 "Res" hs0805long 125.73,168.275 r90 top
R18 "Res" hs0805long 130.175,151.13 r180 top
R19 "Res" hs0805long 128.27,168.275 r90 top
R20 "Res" hs0805long 145.415,163.83 r90 top
R21 "Res" hs0805long 123.19,168.275 r90 top
R22 "Res" hs0805long 121.92,154.94 r90 top
R23 "Res" hs0805long 120.65,168.275 r90 top
R24 "Res" hs0805long 147.955,163.83 r270 top
R25 "Res" hs0805long 88.265,124.46 r180 top
R26 "Res" hs0805long 99.06,93.345 r90 top
R27 "Res" hs0805long 102.87,168.275 r90 top
R28 "Res" hs0805long 104.14,151.13 r180 top
R29 "Res" "Res 0.4\"" 74.295,122.555 r0 top
R30 "Res" hs0805long 74.295,139.7 r0 top
R31 "Res" hs0805long 105.41,168.275 r90 top
R32 "Res" hs0805long 66.04,112.395 r0 top
R33 "Res" hs0805long 64.135,127.635 r270 top
R34 "Res" hs0805long 100.33,168.275 r90 top
R35 "Res" hs0805long 66.04,117.475 r0 top
R36 "Res" hs0805long 64.135,133.35 r90 top
R37 "Res" hs0805long 96.52,154.94 r90 top
R38 "Res" hs0805long 97.79,168.275 r90 top
R39 "Res" hs0805long 68.58,155.575 r270 top
R40 "Res" hs0805long 80.01,156.21 r270 top
R41 "Res" hs0805long 92.71,168.275 r90 top
R42 "Res" hs0805long 93.345,151.13 r180 top
R43 "Res" hs0805long 95.25,168.275 r90 top
R44 "Res" hs0805long 74.93,164.465 r90 top
R45 "Res" hs0805long 90.17,168.275 r90 top
R46 "Res" hs0805long 85.09,154.94 r90 top
R47 "Res" hs0805long 87.63,168.275 r90 top
R48 "Res" hs0805long 75.565,151.13 r180 top
R49 "Res" hs0805long 137.795,125.095 r0 top
R50 "Res" hs0805long 139.065,140.97 r90 top
R51 "Res" hs0805long 72.39,125.095 r0 top
R52 "Res" hs0805long 70.485,140.97 r90 top
R53 "Res" HS0805Long 140.97,186.055 r270 top
R54 "Res" HS0805Long 143.51,186.055 r270 top
RL1 "9901 relay" "9901 Relay" 118.745,116.84 r0 top
RL2 "9901 relay" "9901 Relay" 102.235,116.84 r0 top
U1 "MAR-6SM" ww107 123.19,102.235 r180 top
U2 "AD8672ARZ" "SOIC 8" 116.205,155.575 r270 top
U3 "LT1028" "SOIC 8" 142.875,116.84 r270 top
U4 "LT1028" "SOIC 8" 142.875,135.255 r270 top
U5 "LT1028" "SOIC 8" 146.05,155.575 r270 top
U6 "AD8672ARZ" "SOIC 8" 127.635,155.575 r270 top
U7 "MAR-6SM" ww107 92.71,102.235 r180 top
U8 "AD8672ARZ" "SOIC 8" 102.235,155.575 r270 top
U9 "LT1028" "SOIC 8" 74.295,116.84 r270 top
U10 "LT1028" "SOIC 8" 74.295,135.255 r270 top
U11 "LT1028" "SOIC 8" 74.295,155.575 r270 top
U12 "AD8672ARZ" "SOIC 8" 90.805,155.575 r270 top
U13 "AD620" "SOIC 8" 156.845,167.64 r270 top
X1 "TestPoint" "SM Test point" 126.365,121.92 r0 top
X2 "TestPoint" "SM Test point" 129.54,85.725 r0 top
X3 "TestPoint" "SM Test point" 131.445,171.45 r90 top
X4 "TestPoint" "SM Test point" 116.84,147.955 r90 top
X5 "TestPoint" "SM Test point" 149.86,130.81 r90 top
X6 "TestPoint" "SM Test point" 132.554,166.37 r0 top
X7 "TestPoint" "SM Test point" 128.905,147.955 r0 top
X8 "TestPoint" "SM Test point" 106.045,187.325 r0 top
X9 "TestPoint" "SM Test point" 102.235,187.325 r0 top
X10 "TestPoint" "SM Test point" 127.635,187.325 r0 top
X11 "TestPoint" "SM Test point" 92.71,123.825 r0 top
X12 "TestPoint" "SM Test point" 99.06,85.725 r0 top
X13 "TestPoint" "SM Test point" 78.105,180.975 r0 top
X14 "TestPoint" "SM Test point" 102.87,147.955 r90 top
X15 "TestPoint" "SM Test point" 67.31,127 r90 top
X16 "TestPoint" "SM Test point" 78.105,167.892 r0 top
X17 "TestPoint" "SM Test point" 92.075,147.955 r0 top

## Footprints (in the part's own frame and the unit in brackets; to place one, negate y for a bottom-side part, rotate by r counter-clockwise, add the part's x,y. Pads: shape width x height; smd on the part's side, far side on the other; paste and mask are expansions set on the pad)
"2 way 0.1\"" [mm] "two wire component!"
  round 1.905 hole 1: 1(-1.27,0) 2(1.27,0)
  silkscreen extent -2.67,-1.4 2.67,1.4
"9901 Relay" [mil] "SM reed relay"
  rect 100x25 smd: 1(-140,60) 2(140,60) 5(-140,-20) 6(140,-20)
  silkscreen extent -160,-100 160,100
BOLT [mm] "M3 mounting bolt"
  round 6 hole 3.2: 1(0,0)
  silkscreen extent -3.5,-3.5 3.5,3.5
"D Plug Straight PCB 9 Way" [mil] "D Plug Straight PCB 9 Way"
  round 75 hole 39.37: 1(-218,56) 2(-109,56) 3(0,56) 4(109,56) 5(218,56) 6(-163.5,-56) 7(-54.5,-56) 8(54.5,-56) 9(163.5,-56)
  round 275.59 hole 125.98: 10(-489,0) 10(489,0)
  silkscreen extent -564,-247 564,247
"D Socket Straight PCB 25 Way" [mil] "D socket Straight PCB 25 Way"
  round 75 / inner round 60 / far side round 75 hole 39.37: 1(654,56) 2(545,56) 3(436,56) 4(327,56) 5(218,56) 6(109,56) 7(0,56) 8(-109,56) 9(-218,56) 10(-327,56) 11(-436,56) 12(-545,56) 13(-654,56) 14(599.5,-56) 15(490.5,-56) 16(381.5,-56) 17(272.5,-56) 18(163.5,-56) 19(54.5,-56) 20(-54.5,-56) 21(-163.5,-56) 22(-272.5,-56) 23(-381.5,-56) 24(-490.5,-56) 25(-599.5,-56)
  round 275.59 hole 125.98: 26(-925,0) 26(925,0)
  silkscreen extent -1000,-247 1000,247
DO214AC [mm] "DO214AC"
  rect 2.5x1.8 smd: 1(-2.4,0) 2(2.4,0)
  silkscreen extent -4,-1.5 4,1.5
HS0805Long [mil] "0805 on big pads for hand soldering will also take 1206"
  rect 60x60 smd: 1(-50,0) 2(50,0)
  silkscreen extent -90,-40 90,40
hs0805long [mil] "0805 on big pads for hand soldering will also take 1206"
  rect 60x60 smd: 1(-50,0) 2(50,0)
  silkscreen extent -90,-40 90,40
HS1210 [mil] "Tant case B (A will also fit!)"
  rect 70x90 smd: 1(-50,0) 2(75,0)
  silkscreen extent -100,-60 125,60
"MKS2 7.2 8.5" [mm] "MKS2 7.2 by 8.5"
  round 1.905 hole 0.8: 1(-2.5,0) 2(2.5,0)
  silkscreen extent -3.75,-4.25 3.75,4.25
"MKS2 7.2 11" [mm] "MKS2 7.2 by 11 by 16"
  round 1.905 hole 0.8: 1(-2.5,0) 2(2.5,0)
  silkscreen extent -3.75,-5.5 3.75,5.5
"PCB SMB" [mm] "PCB mount SMB connector"
  round 2.032 hole 1.2: 1(0,0)
  round 2.54 hole 1.7: 2(-2.54,-2.54) 2(-2.54,2.54) 2(2.54,-2.54) 2(2.54,2.54)
  silkscreen extent -4.45,-4.45 4.45,4.45
"Res 0.4\"" [mil] "Wire eneded 0.6W resistor"
  round 60 hole 31.5: 1(-200,0) 2(200,0)
  silkscreen extent -160,-30 155,30
"SM Test point" [mm] "SM Test point 100 x 100mil"
  rrect50% 2x2 smd: 1(0,0)
  silkscreen extent -1.5,-1.5 1.5,1.5
SMA [mm] "SMA Diode"
  rect 2x1.65 smd: 1(-2.3,0) 2(2.3,0)
  silkscreen extent -2.2,-1.5 2.2,1.5
SOD123 [mm] "SOD123 Diode (500mW Zener etc)"
  rect 1.5x0.95 smd: 1(-1.875,0) 2(1.875,0)
  silkscreen extent -3,-1 3,1
"SOIC 8" [mil] "SOIC 8"
  rect 30x75 smd: 1(-75,-112.5) 2(-25,-112.5) 3(25,-112.5) 4(75,-112.5) 5(75,112.5) 6(25,112.5) 7(-25,112.5) 8(-75,112.5)
  silkscreen extent -100,-60 100,60
ww107 [mil] "Mini circuits MAR-6SM"
  rect 66x120 smd: 1(0,-107) 3(0,107)
  rect 25x25 hole 19.68: 2(25,0) 2(83,-47) 2(83,47) 2(138,-47) 2(138,0) 2(138,47) 4(-138,-47) 4(-138,0) 4(-138,47) 4(-83,-47) 4(-83,47) 4(-25,0)
  rect 60x40 smd: 2(77,0) 4(-77,0)
  Top Layer region: -158,70 -158,-70 -71,-70 -61,-60 -61,-25 -5,-25 -5,25 -61,25 -61,60 -71,70
  Top Layer region: 158,70 158,-70 71,-70 61,-60 61,-25 5,-25 5,25 61,25 61,60 71,70
  silkscreen extent -160,-175 160,175

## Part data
C1 C2 C3 C4 C5 C6 C7 C8 C9 C10 C11 C12 C13 C14 C15 C16 C17 C18 C19 C20 C21 C22 C23 C24 C25 C26 C27 C28 C29 C30 C31 C32 C33 C34 C35 C36 C37 C38 C39 C40 C41 C42 C43 C44 C45 C46 C47 C48 C49 C50 C51 C52 C53 C54 C55 C56 C57 C58: "Cap 0.2\" pitch"
D1 D3 D8 D9 D12 D14: library part "Sckottky Diode"
D2 D10 D11 D13: "TVS"
D4 D5 D6 D7 D15 D16 D17 D18: library part 1N4004
J1 J2: library part "PCB SMB"
U2 U6 U8 U12: library part DualOpAmp
U3 U4 U5 U9 U10 U11: library part SingleOpAmp

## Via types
v1: diameter 1.27, hole 0.711, Top Layer to Bottom Layer, 53 vias
v2: diameter 1.27, hole 0.8, Top Layer to Bottom Layer, 25 vias

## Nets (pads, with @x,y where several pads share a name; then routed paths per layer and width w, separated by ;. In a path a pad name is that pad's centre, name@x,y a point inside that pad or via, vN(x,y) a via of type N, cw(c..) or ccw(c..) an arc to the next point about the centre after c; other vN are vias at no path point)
+15V: C2.1 C4.1 C9.1 C10.1 C19.1 C22.1 C31.1 C33.1 C38.1 C39.1 C48.1 C51.1 C57.2 D8.1 R2.2 R26.2 U2.8 U3.7 U4.7 U5.7 U6.8 U8.8 U9.7 U10.7 U11.7 U12.8 U13.7 | length 73.5
  Top Layer w0.635: U13.7 C57.2 v2(162.56,170.18)
  Top Layer w0.762: C51.1 74.93,159.385 v1(74.93,158.115) 74.93,156.845 75.565,156.21 U11.7 ; U9.7 C38.1 v1(81.915,117.475) ; U10.7 C39.1 v1(82.55,135.89) ; v1(93.599,159.131) v1@93.98,158.75 ; U12.8 93.662,158.433 v1@93.98,158.75 ; C48.1 v1@93.98,158.75 ; 100.33,94.615 v1(100.33,97.155) ; v1(105.029,159.131) v1@105.41,158.75 ; U8.8 105.093,158.433 v1@105.41,158.75 ; C33.1 v1@105.41,158.75 ; U2.8 119.062,158.686 v1(119.38,159.004) 119.634,158.75 C4.1 ; U6.8 133.35,157.48 ; v1(133.35,156.845) 133.35,157.48 ; C19.1@133.35,158.75 133.35,157.48 ; v1(144.78,160.02) C22.1 146.685,156.21 U5.7 ; U3.7 C9.1 v1(150.495,117.475) ; U4.7 C10.1 v1(150.495,135.89)
  Top Layer w1.016: R26.2 100.33,94.615 C31.1
  Top Layer w1.27: D8.1 126.125,184.15 129.54,184.15 v2(130.81,185.42) ; R2.2 C2.1 v1(133.985,94.615)
+15VIN: J3.8 J3.12 L5.1 X8.1 | length 55.6
  Top Layer w0.508: X8.1 107.95,187.325 108.585,186.69 v2(108.585,185.42) L5.1
  Dummy Power w0.508: J3.12 93.98,176.042 93.98,174.625 ; J3.8 105.029,174.879 104.14,173.99 94.615,173.99 93.98,174.625 ; v2(108.585,185.42) 106.68,187.325 95.25,187.325 88.9,180.975 88.9,175.26 90.17,173.99 93.345,173.99 93.98,174.625
-15V: C15.1 C17.1 C18.1 C24.1 C27.1 C44.1 C46.1 C47.1 C53.1 C56.1 C58.1 D9.2 U2.4 U3.4 U4.4 U5.4 U6.4 U8.4 U9.4 U10.4 U11.4 U12.4 U13.4 | length 95.5
  Top Layer w0.635: C44.1 69.85,114.3 70.485,114.935 U9.4 ; U10.4 72.39,133.35 C46.1 ; U12.4 88.9,153.67 89.535,153.035 C56.1 ; U8.4 100.33,153.67 C47.1 100.33,149.225 v1(99.695,148.59) ; U2.4 114.3,153.67 C18.1 114.3,149.225 v1(113.665,148.59) ; U6.4 126.365,153.67 C27.1 126.365,149.225 v1(125.73,148.59) ; v1(137.16,114.935) U3.4 140.335,114.617 C15.1 ; v1(137.16,133.35) U4.4 139.7,133.032 C17.1 ; v1(141.605,149.225) 142.875,149.225 143.51,149.86 143.51,153.352 U5.4 ; U13.4 154.305,165.417 C58.1 v2(156.845,163.195)
  Top Layer w0.762: U11.4 71.755,153.352 C53.1
  Top Layer w1.016: v1(69.85,110.49) C44.1
  Top Layer w1.27: v1(71.755,149.225) C53.1 ; C46.1 v1(74.295,130.81) ; v1(80.645,186.055) D9.2 ; v1(87.63,148.59) 88.265,148.59 89.535,149.86 C56.1
  Bottom Layer w0.635: v1(141.605,149.225) 153.67,149.225 158.115,153.67 158.115,161.925 v2(156.845,163.195)
-15VIN: J3.7 J3.11 L6.1 X9.1 | length 30
  Top Layer w0.254: L6.1 L6.1@105.029,182.626
  Top Layer w0.508: X9.1 v2(104.775,184.785) L6.1
  Dummy Power w0.254: J3.11 96.723,180.543 97.155,180.975 104.775,180.975 ; v2(104.775,184.785) 104.775,180.975 ; J3.7 107.798,180.492 107.315,180.975 104.775,180.975
BIASIN1: J3.6 L3.1 X3.1 | length 28.1
  Top Layer w0.305: v2(129.54,172.085) 130.175,171.45 X3.1
  Top Layer w0.508: X3.1 L3.1@134.62,171.45
  Bottom Layer w0.305: J3.6 110.566,175.184 110.566,173.279 111.125,172.72 118.745,172.72 120.015,171.45 128.905,171.45 v2(129.54,172.085)
BIASIN2: J3.10 L9.1 X13.1 | length 28.9
  Top Layer w0.305: L9.1 79.375,177.165 80.01,176.53 80.01,175.895 82.55,173.355 87.63,173.355 88.265,173.99 98.425,173.99 99.492,175.057 J3.10
  Top Layer w0.635: L9.1 X13.1
BIASMON1+: J3.3 R17.2 R19.2 | length 14.5
  Top Layer w0.305: J3.3 118.872,174.498 119.38,173.99 123.825,173.99 125.73,172.085 R17.2
  Top Layer w0.762: R17.2 R19.2
BIASMON1-: J3.15 R21.2 R23.2 | length 12.1
  Top Layer w0.305: R23.2 v2(120.65,172.72)
  Top Layer w0.762: R23.2 R21.2
  Bottom Layer w0.203: 120.256,174.866 J3.15
  Bottom Layer w0.305: 120.256,174.866 120.65,174.473 v2(120.65,172.72)
BIASMON2+: J3.5 R41.2 R43.2 | length 26.2
  Top Layer w0.305: R43.2 95.25,172.085 95.885,172.72 112.395,172.72 113.335,173.66 J3.5
  Top Layer w0.762: R41.2 R43.2
BIASMON2-: J3.17 R45.2 R47.2 | length 35.1
  Top Layer w0.305: R45.2 90.17,172.72 90.805,173.355 111.125,173.355 v2(111.76,173.99)
  Top Layer w0.762: R47.2 R45.2
  Bottom Layer w0.203: 114.719,175.044 J3.17
  Bottom Layer w0.305: v2(111.76,173.99) 113.665,173.99 114.719,175.044
GND: Bolt1.1 Bolt2.1 Bolt3.1 Bolt4.1 C2.2 C4.2 C5.2 C9.2 C10.2 C15.2 C17.2 C18.2 C19.2 C21.1 C22.2 C24.2 C27.2 C28.2 C29.2 C31.2 C33.2 C34.2 C38.2 C39.2 C44.2 C46.2 C47.2 C48.2 C50.1 C51.2 C53.2 C56.2 C57.1 C58.2 D2.2 D3.2 D6.2 D7.1 D10.1 D11.1 D13.2 D14.2 D17.2 D18.1 D19.2 D20.2 J1.2 J2.2 J3.4 J3.16 J3.19 J3.20 J3.23 J3.24 J3.26 J4.3 J4.6 J4.7 J4.8 J4.9 J4.10 L4.1 L10.1 R24.1 R48.1 R53.1 R54.1 RL1.2 RL2.2 U1.2 U1.4 U2.3 U3.3 U4.3 U6.3 U7.2 U7.4 U8.3 U9.3 U10.3 U12.3 U13.5 X10.1 | length 273.8
  Top Layer w0.305: v1(68.58,133.985) 69.215,134.62 U10.3 ; U9.3 73.66,116.205 74.295,115.57 v1(74.295,112.395) ; C56.2 86.995,152.4 86.36,153.035 86.36,154.94 U12.3 ; C47.2 97.79,154.94 U8.3 ; C18.2 111.76,154.94 U2.3 ; C27.2 123.825,151.765 123.19,152.4 123.19,154.94 U6.3 ; v1(133.985,115.189) 135.001,116.205 U3.3 ; 135.89,130.81 135.89,133.985 136.525,134.62 U4.3
  Top Layer w0.381: RL2.2 105.791,119.126 v2(106.68,120.015) ; v2(121.92,120.65) 122.301,120.269 RL1.2
  Top Layer w0.635: U13.5 C57.1
  Top Layer w0.762: C50.1 63.328,151.13 C53.2 ; D17.2 67.945,98.425 73.025,93.345 L10.1 ; v1(68.58,169.545) 70.98,169.545 D13.2 74.435,169.685 74.93,170.18 D14.2 ; R48.1 v1(78.74,151.13) ; C51.2 v1(78.105,162.56) ; C39.2 v1(80.645,140.335) ; C34.2 v1(82.55,170.815) ; v1(85.09,150.495) 85.725,151.13 C56.2 ; v1(86.995,182.245) C29.2 ; C48.2 v1(98.425,161.29) ; v1(97.155,148.59) 97.79,149.225 C47.2 ; v1(106.68,161.29) C33.2 ; v1(111.125,149.225) 111.76,149.86 C18.2 ; D10.1 118.745,186.69 119.38,187.325 v1(121.285,187.325) X10.1 ; v1(120.015,161.29) C4.2 ; v1(123.19,149.225) 123.825,149.86 C27.2 ; v1(133.985,115.189) D7.1 134.125,112.395 C15.2 ; v1(135.255,130.81) 135.89,130.81 C17.2 ; D3.2 141.08,175.29 141.605,174.765 141.605,168.275 ; v2(138.43,187.325) R53.1 R54.1 ; L4.1 142.875,92.075 144.145,93.345 D6.2 ; 144.78,167.64 147.32,167.64 147.955,167.005 R24.1 151.13,165.1 151.765,164.465 151.765,160.655 151.13,160.02 C22.2 ; C24.2 v1(148.59,151.13) ; C9.2 v1(150.495,120.015) ; C10.2 150.495,138.43 v1(151.13,139.065)
  Top Layer w1.016: v1(68.58,133.985) 68.58,132.08 C46.2 ; C44.2 v1(74.295,112.395) ; C38.2 v1(81.915,120.015) ; D18.1 84.595,106.54 v1(86.36,104.775) ; D20.2 94.615,111.76 v2(95.885,110.49) ; J2.2@95.098,88.265 100.33,88.265 101.6,89.535 C31.2 ; D11.1 v1(98.425,186.055) ; v2(107.95,113.03) 110.35,113.03 D19.2 ; J1.2@125.578,88.265 129.54,88.265 131.445,90.17 C2.2 ; C19.2@133.35,161.29 134.62,161.29 v1(135.255,161.925) ; 141.605,168.275 v2(142.875,168.275) 144.145,168.275 144.78,167.64 ; 151.765,160.655 C58.2 ; v2(162.56,163.83) C57.1
  Dummy Ground w0.381: J3.26@84.303,177.49 84.303,179.553 v1(86.995,182.245) 86.995,181.61 87.643,180.962 117.488,180.962 ; J3.4 116.103,177.528 J3.16 117.488,180.962 ; J3.26@131.293,177.49 127.821,180.962 117.488,180.962
NetC1_2: C1.2 U1.1 | length 3.6
  Top Layer w0.635: U1.1 C1.2
NetC3_1: C3.1 L1.1 U1.3 | length 7.7
  Top Layer w0.508: C3.1 C3.1@123.19,95.25 ; U1.3 C3.1@123.19,95.25 ; L1.1 C3.1@123.19,95.25
NetC3_2: C3.2 J1.1 X2.1 | length 13.1
  Top Layer w0.508: C3.2 123.038,91.592 J1.1 X2.1
NetC6_1: C6.1 R49.2 | length 2.5
  Top Layer w0.305: R49.2 C6.1
NetC6_2: C6.2 R5.2 R9.1 R12.1 U3.6 X5.1 | length 33.8
  Top Layer w0.305: U3.6 144.145,116.205 143.51,116.84 143.51,120.015 144.145,120.65 146.05,120.65 R5.2 147.955,123.825 146.685,125.095 C6.2 144.145,129.54 145.415,130.81 X5.1 R9.1 R12.1
NetC7_1: C7.1 R50.2 | length 2.5
  Top Layer w0.305: R50.2 C7.1
NetC7_2: C7.2 R4.1 R6.2 R13.1 U2.5 U4.6 X4.1 | length 60.1
  Top Layer w0.305: R13.1 110.49,152.4 109.855,151.765 109.855,147.955 110.49,147.32 116.205,147.32 X4.1 118.745,147.955 ; U2.5 119.38,153.352 R4.1 119.38,148.59 118.745,147.955 ; U4.6 144.145,134.62 143.51,135.255 143.51,137.795 144.145,138.43 R6.2 C7.2 144.145,144.145 142.875,145.415 121.285,145.415 118.745,147.955
NetC8_1: C8.1 R3.1 R4.2 U2.6 | length 18.6
  Top Layer w0.305: R3.1 C8.1 115.57,161.925 116.205,161.29 116.205,155.575 116.84,154.94 ; R4.2 116.84,154.94 ; U2.6 116.84,154.94
NetC8_2: C8.2 R7.1 U2.7 | length 13.2
  Top Layer w0.305: R7.1 C8.2 118.11,162.56 116.84,161.29 116.84,156.845 117.475,156.21 U2.7
NetC11_1: C11.1 C14.1 D4.2 D6.1 L2.1 L4.2 R8.1 | length 66.5
  Top Layer w0.305: L2.1 v1(135.255,120.65) ; R8.1 156.25,102.87 ; C11.1 156.25,102.87 ; C14.1 156.25,102.87
  Top Layer w0.508: L4.2 D4.2 140.83,97.93 141.605,98.705 141.605,102.235 142.24,102.87 R8.1
  Bottom Layer w0.305: v1(135.255,120.65) 142.875,113.03 C14.1
NetC11_2: C11.2 C14.2 R11.1 | length 24.5
  Top Layer w0.305: R11.1 153.035,113.665 154.305,114.935 160.02,114.935 161.25,113.705 C14.2 C11.2
NetC12_1: C12.1 C16.1 R12.2 | length 20.3
  Top Layer w0.305: R12.2 161.25,136.525 ; C16.1 161.25,136.525 ; C12.1 161.25,136.525
NetC12_2: C12.2 C16.2 R6.1 R9.2 R50.1 U4.2 | length 47
  Top Layer w0.305: U4.2 137.795,135.89 v2(137.16,136.525) 137.16,139.065 137.795,139.7 R50.1 R6.1 ; R9.2 155.575,128.27 156.25,127.595 C16.2
  Bottom Layer w0.305: v2(137.16,136.525) 137.795,137.16 152.4,137.16 153.67,138.43 C12.2 C16.2
NetC13_1: C13.1 R10.1 R13.2 U2.2 | length 16.6
  Top Layer w0.305: R13.2 U2.2 114.935,156.21 115.57,156.845 115.57,159.385 113.03,161.925 C13.1 R10.1
NetC13_2: C13.2 R14.1 U2.1 | length 10.7
  Top Layer w0.305: R14.1 C13.2 110.49,162.56 113.347,159.702 U2.1
NetC20_1: C20.1 R15.1 R16.1 U5.2 | length 23.5
  Top Layer w0.305: R15.1 140.335,156.21 U5.2 144.78,156.21 v1(145.415,155.575) ; R16.1 C20.1 v1(156.845,157.48)
  Bottom Layer w0.305: v1(145.415,155.575) 154.94,155.575 v1(156.845,157.48)
NetC20_2: C20.2 R16.2 R18.1 R22.1 U5.6 U6.5 X7.1 | length 54
  Top Layer w0.305: R22.1 121.92,147.955 122.555,147.32 130.81,147.32 131.445,147.955 ; U6.5 130.493,153.352 131.445,152.4 R18.1 131.445,147.955 ; U5.6 R16.2 ; C20.2 R16.2 ; 131.445,147.955 132.08,147.32 149.225,147.32 151.765,149.86 R16.2
NetC21_2: C21.2 R15.2 | length 2.7
  Top Layer w0.305: C21.2 137.118,156.803 R15.2
NetC23_1: C23.1 R17.1 R18.2 U6.6 | length 18.8
  Top Layer w0.305: R17.1 C23.1 125.73,160.655 127.635,158.75 127.635,156.21 128.905,154.94 ; R18.2 128.905,154.94 ; U6.6 128.905,154.94
NetC23_2: C23.2 R19.1 U6.7 | length 12.6
  Top Layer w0.305: R19.1 C23.2 128.27,156.845 128.905,156.21 U6.7
NetC25_2: C25.2 R20.1 R24.2 U5.3 | length 30.1
  Top Layer w0.305: U5.3 141.605,154.94 139.7,153.035 139.7,152.4 139.065,151.765 135.89,151.765 135.255,152.4 135.255,158.115 137.2,160.06 C25.2 139.74,160.06 142.24,162.56 R20.1 R24.2
NetC26_1: C26.1 R21.1 R22.2 U6.2 | length 17.1
  Top Layer w0.305: R22.2 U6.2 126.365,156.21 127,156.845 127,158.115 125.095,160.02 125.095,162.56 C26.1 R21.1
NetC26_2: C26.2 R23.1 U6.1 | length 12.4
  Top Layer w0.305: R23.1 C26.2 120.65,163.195 121.285,162.56 123.19,162.56 123.825,161.925 123.825,159.385 124.777,158.433 U6.1
NetC28_1: C28.1 D8.2 D10.2 L5.2 | length 12.8
  Top Layer w0.508: L5.2 113.03,184.15 113.805,184.15 ; D10.2 113.805,184.15 ; D8.2 117.475,182.88 117.475,184.15 113.805,184.15
NetC29_1: C29.1 D9.1 D11.2 L6.2 | length 18
  Top Layer w1.27: D9.1 D11.2 91.44,185.56 C29.1 96.52,182.245 97.155,182.88 L6.2
NetC30_2: C30.2 U7.1 | length 3.6
  Top Layer w0.635: U7.1 C30.2
NetC32_1: C32.1 L7.1 U7.3 | length 8.3
  Top Layer w0.635: U7.3 C32.1 93.345,95.25 L7.1
NetC32_2: C32.2 J2.1 X12.1 | length 12.9
  Top Layer w0.635: C32.2 92.71,85.877 J2.1 X12.1
NetC35_1: C35.1 R51.2 | length 2.5
  Top Layer w0.305: R51.2 C35.1
NetC35_2: C35.2 R29.2 R33.1 R36.1 U9.6 X15.1 | length 34.8
  Top Layer w0.305: R36.1 R33.1 66.675,128.905 67.31,128.27 X15.1 78.105,127 78.74,126.365 C35.2 ; U9.6 75.565,116.205 74.93,116.84 74.93,120.015 75.565,120.65 77.47,120.65 R29.2 79.375,124.587 C35.2@78.867,125.095
NetC36_1: C36.1 R52.2 | length 2.5
  Top Layer w0.305: R52.2 C36.1
NetC36_2: C36.2 R28.1 R30.2 R37.1 U8.5 U10.6 X14.1 | length 59
  Top Layer w0.305: U10.6 75.565,134.62 74.93,135.255 74.93,137.795 75.565,138.43 R30.2 C36.2 75.565,144.145 76.835,145.415 93.345,145.415 95.885,147.955 ; R37.1 96.52,149.86 95.885,149.225 95.885,147.955 ; U8.5 106.68,153.67 106.68,151.13 ; R28.1 106.68,151.13 ; 95.885,147.955 96.52,147.32 102.235,147.32 X14.1 106.045,147.955 106.68,148.59 106.68,151.13
NetC37_1: C37.1 R27.1 R28.2 U8.6 | length 18.6
  Top Layer w0.305: R28.2 102.87,154.94 ; R27.1 C37.1 102.87,161.925 102.235,161.29 102.235,155.575 102.87,154.94 ; U8.6 102.87,154.94
NetC37_2: C37.2 R31.1 U8.7 | length 13.7
  Top Layer w0.305: U8.7 103.505,156.21 102.87,156.845 102.87,160.655 105.41,163.195 C37.2 R31.1
NetC40_1: C40.1 C43.1 D15.2 D17.1 L8.1 L10.2 R32.1 | length 73.3
  Top Layer w1.016: C43.1 55.92,110.49 ; C40.1 55.92,110.49 ; R32.1 64.77,110.49 ; L10.2 75.565,95.25 73.66,97.155 D15.2 71.615,101.74 71.12,102.235 71.12,105.41 69.99,106.54 ; L8.1 86.995,112.395 84.455,109.855 72.39,109.855 69.99,107.455 69.99,106.54 ; 55.92,110.49 64.77,110.49 ; 64.77,110.49 64.77,107.315 65.545,106.54 D17.1 69.99,106.54
NetC40_2: C40.2 C43.2 R35.1 | length 19.6
  Top Layer w1.016: C40.2 60.92,116.165 62.23,117.475 R35.1
  Bottom Layer w1.016: C43.2 C40.2
NetC41_1: C41.1 C45.1 R36.2 | length 20.3
  Top Layer w0.305: C45.1 55.92,134.62 ; C41.1 55.92,134.62 ; R36.2 55.92,134.62
NetC41_2: C41.2 C45.2 R30.1 R33.2 R52.1 U10.2 | length 34.4
  Top Layer w0.305: C45.2 R33.2 ; C41.2 64.77,138.43 67.31,135.89 U10.2 72.39,135.89 73.025,136.525 R30.1 R52.1
  Bottom Layer w0.305: C45.2 C41.2
NetC42_1: C42.1 R34.1 R37.2 U8.2 | length 15.1
  Top Layer w0.305: R37.2 U8.2 100.33,156.21 100.965,156.845 100.965,163.83 C42.1 R34.1
NetC42_2: C42.2 R38.1 U8.1 | length 10.8
  Top Layer w0.305: R38.1 C42.2 97.79,163.195 98.425,162.56 99.06,162.56 99.695,161.925 99.695,157.797 U8.1
NetC49_1: C49.1 R39.1 R40.1 U11.2 | length 23
  Top Layer w0.762: v1(68.58,158.75) R39.1 69.85,156.845 70.485,156.21 U11.2 ; v1(80.01,160.655) R40.1 C49.1
  Bottom Layer w0.762: v1(68.58,158.75) 71.12,158.75 73.025,160.655 v1(80.01,160.655)
NetC49_2: C49.2 R40.2 R42.1 R46.1 U11.6 U12.5 X17.1 | length 32.3
  Top Layer w0.762: U11.6 R40.2 C49.2 82.55,153.67 ; R46.1 82.55,153.67 ; U12.5 93.662,153.352 94.615,152.4 R42.1 94.615,148.59 93.98,147.955 X17.1 90.805,147.955 89.535,146.685 86.36,146.685 82.55,150.495 82.55,153.67
NetC50_2: C50.2 R39.2 | length 6.6
  Top Layer w0.762: C50.2 65.153,154.305 R39.2
NetC52_1: C52.1 R41.1 R42.2 U12.6 | length 19.3
  Top Layer w0.305: 92.075,154.94 90.805,156.21 90.805,160.655 92.71,162.56 C52.1 R41.1
  Top Layer w0.762: R42.2 92.075,152.4 91.44,153.035 91.44,154.305 92.075,154.94 U12.6
NetC52_2: C52.2 R43.1 U12.7 | length 14.2
  Top Layer w0.305: U12.7 92.075,156.21 91.44,156.845 91.44,159.385 95.25,163.195 C52.2 R43.1
NetC54_2: C54.2 R44.1 R48.2 U11.3 | length 20.7
  Top Layer w0.762: C54.2 70.796,162.865 73.66,162.865 ; U11.3 73.558,154.94 73.609,154.991 ; R48.2 74.295,154.305 73.609,154.991 ; R44.1 74.6,162.865 73.66,162.865 ; 73.609,154.991 73.609,158.713 73.66,158.764 73.66,162.865
NetC55_1: C55.1 R45.1 R46.2 U12.2 | length 15.5
  Top Layer w0.305: R46.2 U12.2 89.535,156.21 90.17,156.845 C55.1
  Top Layer w0.762: C55.1 R45.1
NetC55_2: C55.2 R47.1 U12.1 | length 9.7
  Top Layer w0.762: R47.1 C55.2 87.63,161.925 87.947,161.607 U12.1
NetD4_K: D4.1 D5.2 | length 9.1
  Top Layer w1.016: D5.2 135.75,97.93 136.525,98.705 136.525,102.235 137.02,102.73 D4.1
NetD5_K: D5.1 D7.2 | length 4.7
  Top Layer w1.016: D5.1 D7.2
NetD15_K: D15.1 D16.2 | length 8.6
  Top Layer w1.016: D15.1 75.07,106.54 76.2,105.41 76.2,102.87 77.33,101.74 D16.2
NetD16_K: D16.1 D18.2 | length 8.4
  Top Layer w1.016: D16.1 78.88,106.68 80.01,106.68 81.28,105.41 81.28,102.235 81.775,101.74 D18.2
NetL1_2: L1.2 R2.1 | length 3.2
  Top Layer w0.508: L1.2 R2.1
NetL7_2: L7.2 R26.1 | length 3.2
  Top Layer w0.635: L7.2 R26.1
NetR1_1: R1.1 RL1.6 X1.1 | length 13.2
  Top Layer w0.635: RL1.6 124.587,116.332 126.365,118.11 X1.1 126.365,123.825 R1.1
NetR5_1: R5.1 R8.2 R11.2 R49.1 U3.2 | length 34.6
  Top Layer w0.305: R49.1 136.525,123.19 137.16,122.555 R5.1 139.7,120.65 141.605,120.65 142.24,120.015 142.24,118.11 141.605,117.475 ; U3.2 141.605,117.475 ; R8.2 R11.2 145.415,108.585 142.24,111.76 142.24,116.84 141.605,117.475
NetR25_1: R25.1 RL2.6 X11.1 | length 21.9
  Top Layer w0.635: R25.1 92.075,124.46 X11.1 97.155,123.825 98.425,122.555 100.33,122.555 102.235,120.65 102.235,116.84 102.743,116.332 RL2.6
NetR29_1: R29.1 R32.2 R35.2 R51.1 U9.2 | length 18.4
  Top Layer w0.305: R35.2 69.215,117.475 ; R51.1 71.12,123.19 70.485,122.555 R29.1 69.215,117.475 ; U9.2 69.215,117.475
  Top Layer w1.016: R32.2 R35.2
OUT1+: J3.9 R3.2 R7.2 | length 21.2
  Top Layer w0.762: v2(115.57,171.45) R3.2 R7.2
  Bottom Layer w0.305: J3.9 102.26,175.235 103.505,173.99 104.775,173.99 108.585,170.18 114.3,170.18 v2(115.57,171.45)
OUT1-: J3.21 R10.2 R14.2 | length 16.5
  Top Layer w0.305: R14.2 v2(110.49,171.45)
  Top Layer w0.762: R14.2 R10.2
  Bottom Layer w0.203: 103.645,175.26 J3.21
  Bottom Layer w0.305: 103.645,175.26 104.28,174.625 105.41,174.625 108.585,171.45 v2(110.49,171.45)
OUT2+: J3.13 R27.2 R31.2 | length 19.1
  Top Layer w0.305: R27.2 v2(102.87,171.45)
  Top Layer w0.762: R27.2 R31.2
  Bottom Layer w0.305: J3.13 91.186,174.244 92.075,173.355 100.965,173.355 v2(102.87,171.45)
OUT2-: J3.25 R34.2 R38.2 | length 21.4
  Top Layer w0.305: R38.2 v2(97.79,171.45)
  Top Layer w0.762: R38.2 99.06,169.545 R34.2
  Bottom Layer w0.305: J3.25 90.648,178.913 89.535,177.8 89.535,173.99 90.805,172.72 97.155,172.72 97.79,172.085 v2(97.79,171.45)
PHOTODIODE1_PIN1: C1.1 D1.2 J4.5 L2.2 R1.2 | length 58.3
  Top Layer w0.508: J4.5 113.335,137.465 114.3,138.43 124.46,138.43 125.73,137.16 125.73,132.715 126.365,132.08 132.08,132.08 L2.2 129.54,123.825 128.905,123.19 128.905,111.76 C1.1 ; R1.2 D1.2
PHOTODIODE1_PIN2: C5.1 C25.1 D1.1 D2.1 D3.1 J4.4 L3.2 R20.2 X6.1 | length 99.9
  Top Layer w0.508: J4.4 110.566,137.236 113.03,139.7 127,139.7 128.27,138.43 D1.1 ; X6.1 137.503,166.37 ; D2.1@141.605,179.565 141.11,179.07 137.16,179.07 136.525,178.435 136.525,173.99 137.795,172.72 137.795,171.45 C5.1 137.795,166.662 137.503,166.37 ; R20.2 138.773,165.1 137.503,166.37
  Bottom Layer w0.508: J4.4 110.566,140.411 135.255,165.1 138.773,165.1 C25.1
PHOTODIODE2_PIN1: C30.1 D12.2 J4.2 L8.2 R25.2 | length 59.5
  Top Layer w0.635: C30.1 90.17,118.745 89.535,119.38 L8.2 R25.2 D12.2 86.755,131.445 85.09,131.445 85.09,138.43 86.36,139.7 103.505,139.7 105.029,138.176 J4.2
PHOTODIODE2_PIN2: C34.1 C54.1 D12.1 D13.1 D14.1 J4.1 L9.2 R44.2 X16.1 | length 89.4
  Top Layer w0.635: C54.1 71.746,166.327 72.337,165.735 R44.2 77.47,165.735 ; D13.1 77.61,174.485 L9.2 C34.1 X16.1 78.105,166.37 77.47,165.735 ; v2(84.455,165.1) 78.105,165.1 77.47,165.735 ; D12.1 86.995,137.795 87.63,138.43 100.965,138.43 102.26,137.135 J4.1
  Bottom Layer w0.635: v2(84.455,165.1) 92.075,157.48 92.075,151.13 102.26,140.945 J4.1
RLY1: D19.1 J3.18 RL1.1 | length 136.8
  Top Layer w0.635: D19.1 111.366,118.364 RL1.1 ; RL1.1@115.824,118.364 116.205,118.745 v2(116.205,121.285)
  Bottom Layer w0.635: J3.18 111.95,179.895 114.3,182.245 137.16,182.245 149.86,169.545 153.67,169.545 161.925,161.29 161.925,149.86 153.035,140.97 136.525,140.97 116.84,121.285 v2(116.205,121.285)
RLY2: D20.1 J3.22 RL2.1 | length 87.9
  Top Layer w0.635: v2(95.25,121.92) 94.615,121.285 D20.1 98.438,118.605 RL2.1
  Bottom Layer w0.635: v2(95.25,121.92) 95.25,122.555 89.535,128.27 89.535,154.305 83.82,160.02 83.82,161.925 83.185,162.56 83.185,167.64 88.425,172.88 88.425,179.23 90.805,181.61 100.152,181.61 100.876,180.886 J3.22
TEST+: J3.2 R53.2 U13.3 | length 50.2
  Top Layer w0.305: J3.2 123.05,177.478 125.408,177.478 130.175,182.245 139.7,182.245 140.97,183.515 ; R53.2 140.97,183.515 ; U13.3 149.86,167.005 147.955,168.91 145.415,168.91 144.145,170.18 144.145,181.61 143.51,182.245 142.24,182.245 140.97,183.515
TEST-: J3.14 R54.2 U13.2 | length 59.3
  Top Layer w0.305: J3.14 125.573,178.913 129.54,182.88 135.255,182.88 136.525,184.15 136.525,187.96 137.795,189.23 144.78,189.23 145.415,188.595 145.415,185.42 144.78,184.785 R54.2 143.51,183.515 144.78,182.245 144.78,170.815 146.05,169.545 148.59,169.545 149.86,168.275 U13.2
TESTSIG: RL1.5 RL2.5 U13.6 | length 130.7
  Top Layer w0.635: RL2.5 98.679,112.776 100.33,111.125 114.3,111.125 115.189,112.014 v2(115.189,113.03) RL1.5 ; U13.6 158.115,167.005 157.48,166.37 157.48,165.1 160.655,161.925 v2(160.655,145.415)
  Bottom Layer w0.635: v2(115.189,113.03) 128.27,113.03 131.445,109.855 157.48,109.855 158.75,111.125 158.75,143.51 v2(160.655,145.415)
pads on no net: J3.1 U3.1 U3.5 U3.8 U4.1 U4.5 U4.8 U5.1 U5.5 U5.8 U9.1 U9.5 U9.8 U10.1 U10.5 U10.8 U11.1 U11.5 U11.8 U13.1 U13.8

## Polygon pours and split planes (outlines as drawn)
GND on Bottom Layer "Top Layer-No Net" (solid, remove dead copper, pour order 0): 51.435,76.835 163.83,76.835 163.83,189.23 51.435,189.23
GND on Dummy Ground "Top Layer-No Net" (solid, remove dead copper, pour order 2): 51.435,189.23 163.83,189.23 163.83,76.835 51.435,76.835
-15VIN on Dummy Power "Top Layer-No Net" (solid, pour order 14): 88.265,167.64 111.76,167.64 111.76,191.135 88.265,191.135
+15VIN on Dummy Power "Top Layer-No Net" (solid, remove dead copper, pour order 12): 88.773,168.275 88.773,190.5 111.506,190.5 111.506,168.529 111.379,168.402
+15V on Dummy Power "Top Layer-No Net" (solid, remove dead copper, pour order 6): 51.435,189.23 163.83,189.23 163.83,76.835 51.435,76.835
-15V on Dummy Power "Top Layer-No Net" (solid, remove dead copper, pour order 4): 51.435,189.23 163.83,189.23 163.83,76.835 51.435,76.835
GND on Top Layer "Top Layer-No Net" (solid, remove dead copper, pour order 8): 51.435,76.835 164.465,76.835 164.465,189.865 51.435,189.865

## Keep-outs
Keep-Out Layer:
  lines w0.254: 50.8,91.288 ccw(c65.888,91.288) 65.888,76.2 149.708,76.2 ccw(c149.708,91.288) 164.795,91.288 164.795,175.108 ccw(c149.708,175.108) 149.708,190.195 65.888,190.195 ccw(c65.888,175.108) 50.8,175.108 50.8,91.288

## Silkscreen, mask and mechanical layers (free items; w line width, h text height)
Top Overlay:
  lines w0.254: 96.266,149.987 96.266,152.527 ; 96.52,96.52 97.282,97.282 ; 127.254,96.266 127.254,96.52 127.762,97.028 ; 147.574,153.035 148.59,152.019 149.352,152.019
Mechanical 2:
  lines w0.254: 50.8,91.313 50.8,94.234 ; 50.8,94.209 68.809,94.209 68.809,76.2 ; 50.8,172.187 68.809,172.187 68.809,190.195 ; 50.8,172.212 50.8,175.006 ; 65.913,76.2 68.834,76.2 ; 65.913,190.195 68.834,190.195 ; 146.787,76.2 146.787,94.209 164.795,94.209 ; 146.787,190.195 146.787,172.187 164.795,172.187 ; 146.812,76.2 149.733,76.2 ; 146.812,190.195 149.657,190.195 ; 164.795,91.313 164.795,94.234 ; 164.795,172.212 164.795,175.006 ; 89.789,124.206 125.806,124.206 125.806,142.189 89.789,142.189 89.789,124.206
Mechanical 3:
  rectangle: 50.8,100.178 164.795,166.218
Mechanical 4:
  lines w0.254: 65.888,190.195 ccw(c65.888,175.108) 50.8,175.108 50.8,91.288 ccw(c65.888,91.288) 65.888,76.2 149.708,76.2 ccw(c149.708,91.288) 164.795,91.288 164.795,175.108 ccw(c149.708,175.108) 149.708,190.195 65.913,190.195
Mechanical 10:
  lines w0.508: 86.36,74.93 86.36,101.6 93.345,108.585 136.525,108.585 141.605,113.665 141.605,115.57 140.97,116.205 78.74,116.205 77.47,117.475 77.47,122.555 78.105,123.19 142.24,123.19 143.51,124.46 143.51,139.065 142.24,140.335 90.17,140.335 83.82,133.985 78.74,133.985 78.105,134.62 78.105,145.415 78.74,146.05 142.24,146.05 144.145,147.955 144.145,151.13 142.875,152.4 103.505,152.4 ; 104.775,152.4 74.295,152.4 71.755,154.94 71.755,163.195 76.2,167.64 88.265,167.64 ; 111.633,182.499 109.22,182.499 105.537,186.182 100.838,186.182 95.25,180.594 95.25,174.625 100.965,174.625 100.965,177.165 100.965,177.292 101.219,177.546 106.045,177.546 106.426,177.165 106.426,174.625 106.68,174.371 111.76,174.371 ; 88.265,167.64 111.76,167.64 111.76,191.135 88.265,191.135 88.265,167.64
Mechanical 11:
  lines w0.254: 69.3,76.7 69.3,189.7 ; 69.3,95.2 146.3,95.2 ; 69.3,171.2 146.3,171.2 ; 146.3,76.7 146.3,189.7
Mechanical 16:
  lines w0.254: 88.265,101.6 88.265,99.695 97.155,99.695 97.155,101.6 ; 88.265,102.87 88.265,104.775 97.155,104.775 97.155,102.87 ; 118.745,101.6 118.745,99.695 127.635,99.695 127.635,101.6 ; 118.745,102.87 118.745,104.775 127.635,104.775 127.635,102.87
